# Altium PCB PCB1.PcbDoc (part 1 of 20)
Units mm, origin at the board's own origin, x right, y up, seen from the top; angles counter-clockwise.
Board outline 294.51 x 138.18 mm, 12 copper layers (Top Layer 1 _Signal, L2_GND, L3_Signals, L4_GND, L5_POWER, L6_Signals, L7_GND, L8_Signals, L9_GND, L10_POWER, L11_GND, Bottom Layer_Signals), stack 1.788 mm thick; 1254 components, 836 nets, 5699 pads, 2073 vias.
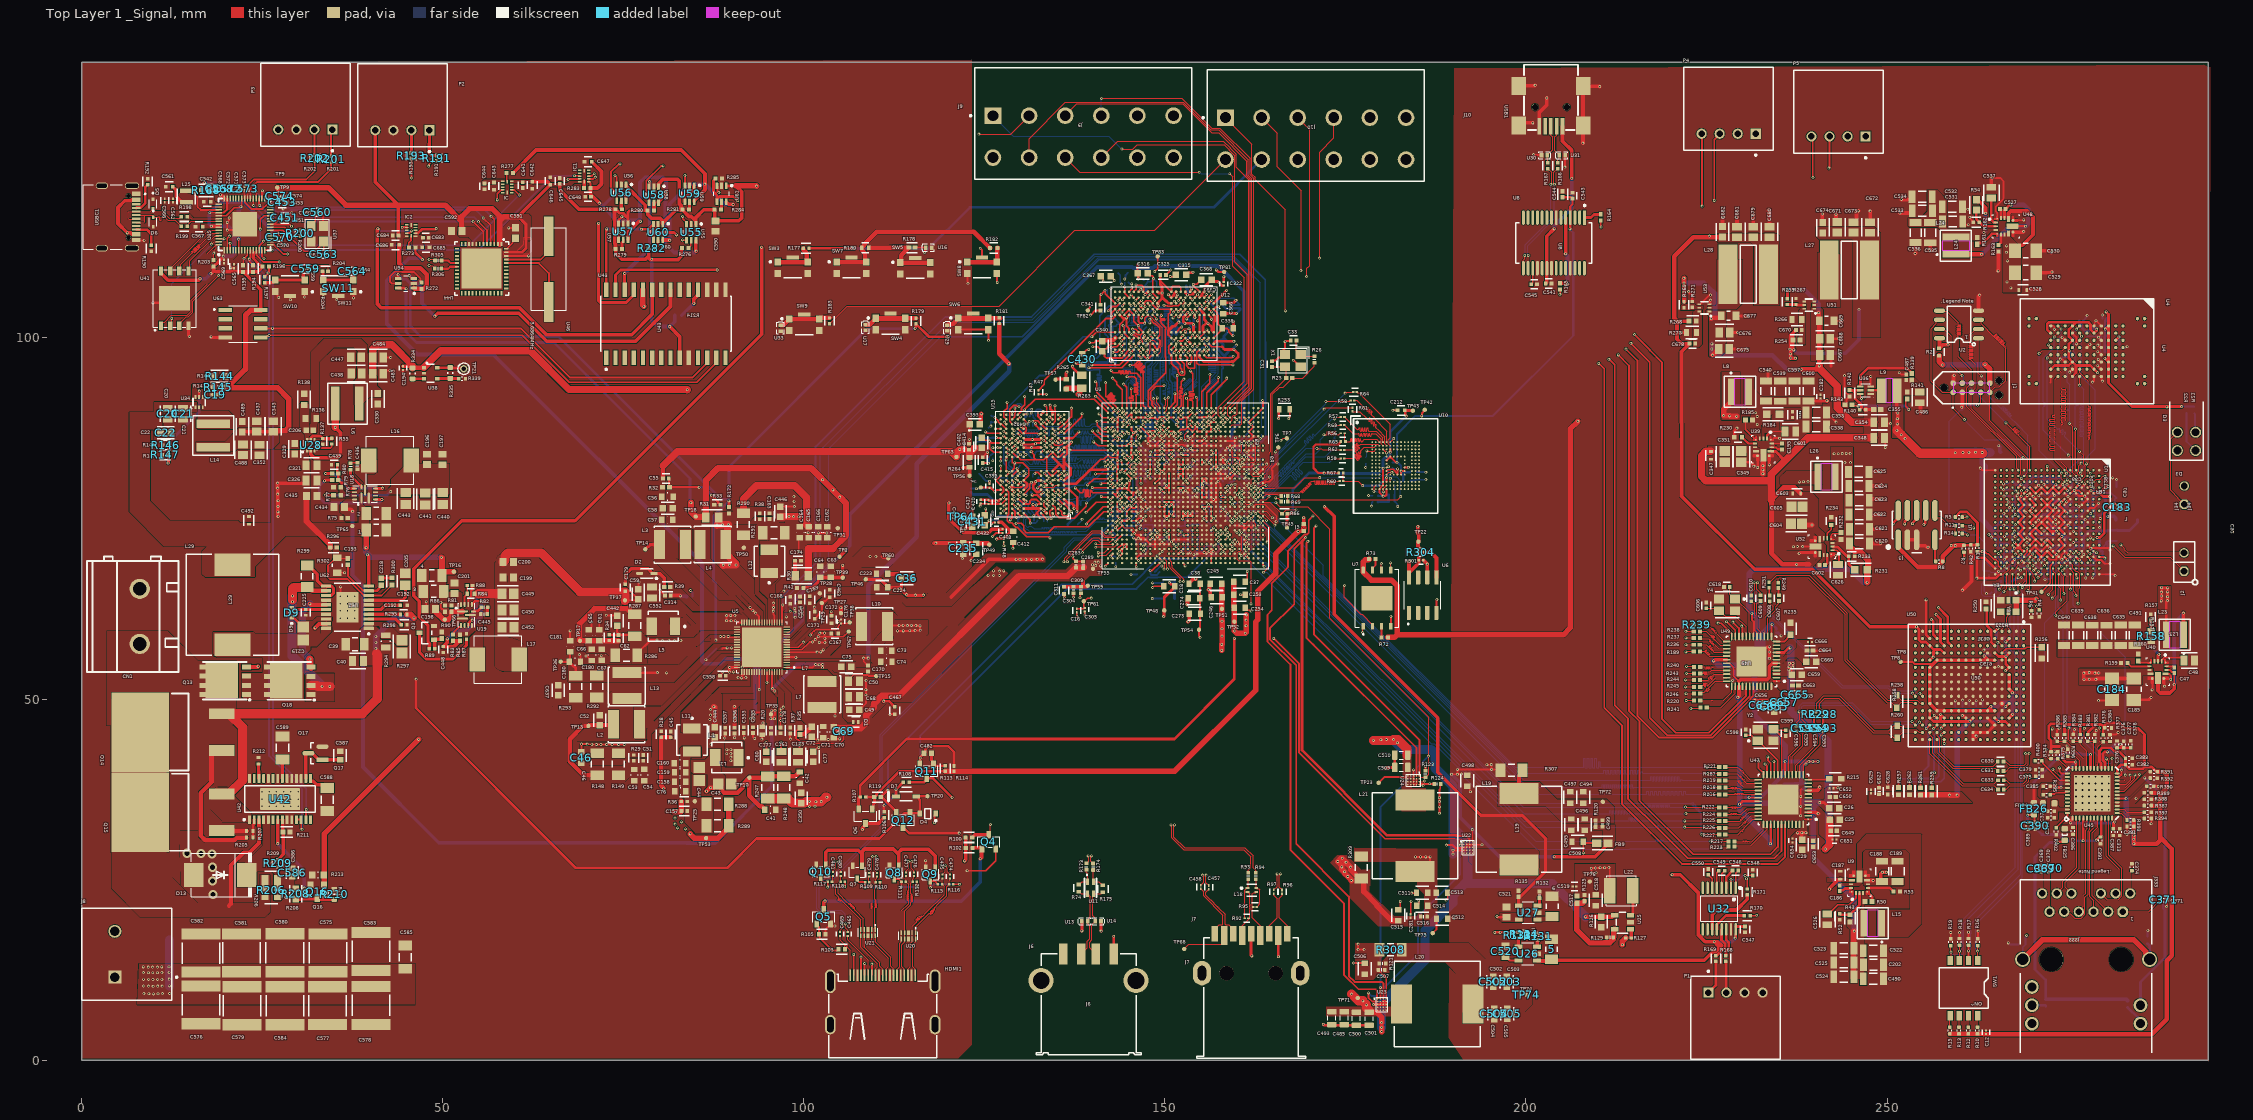
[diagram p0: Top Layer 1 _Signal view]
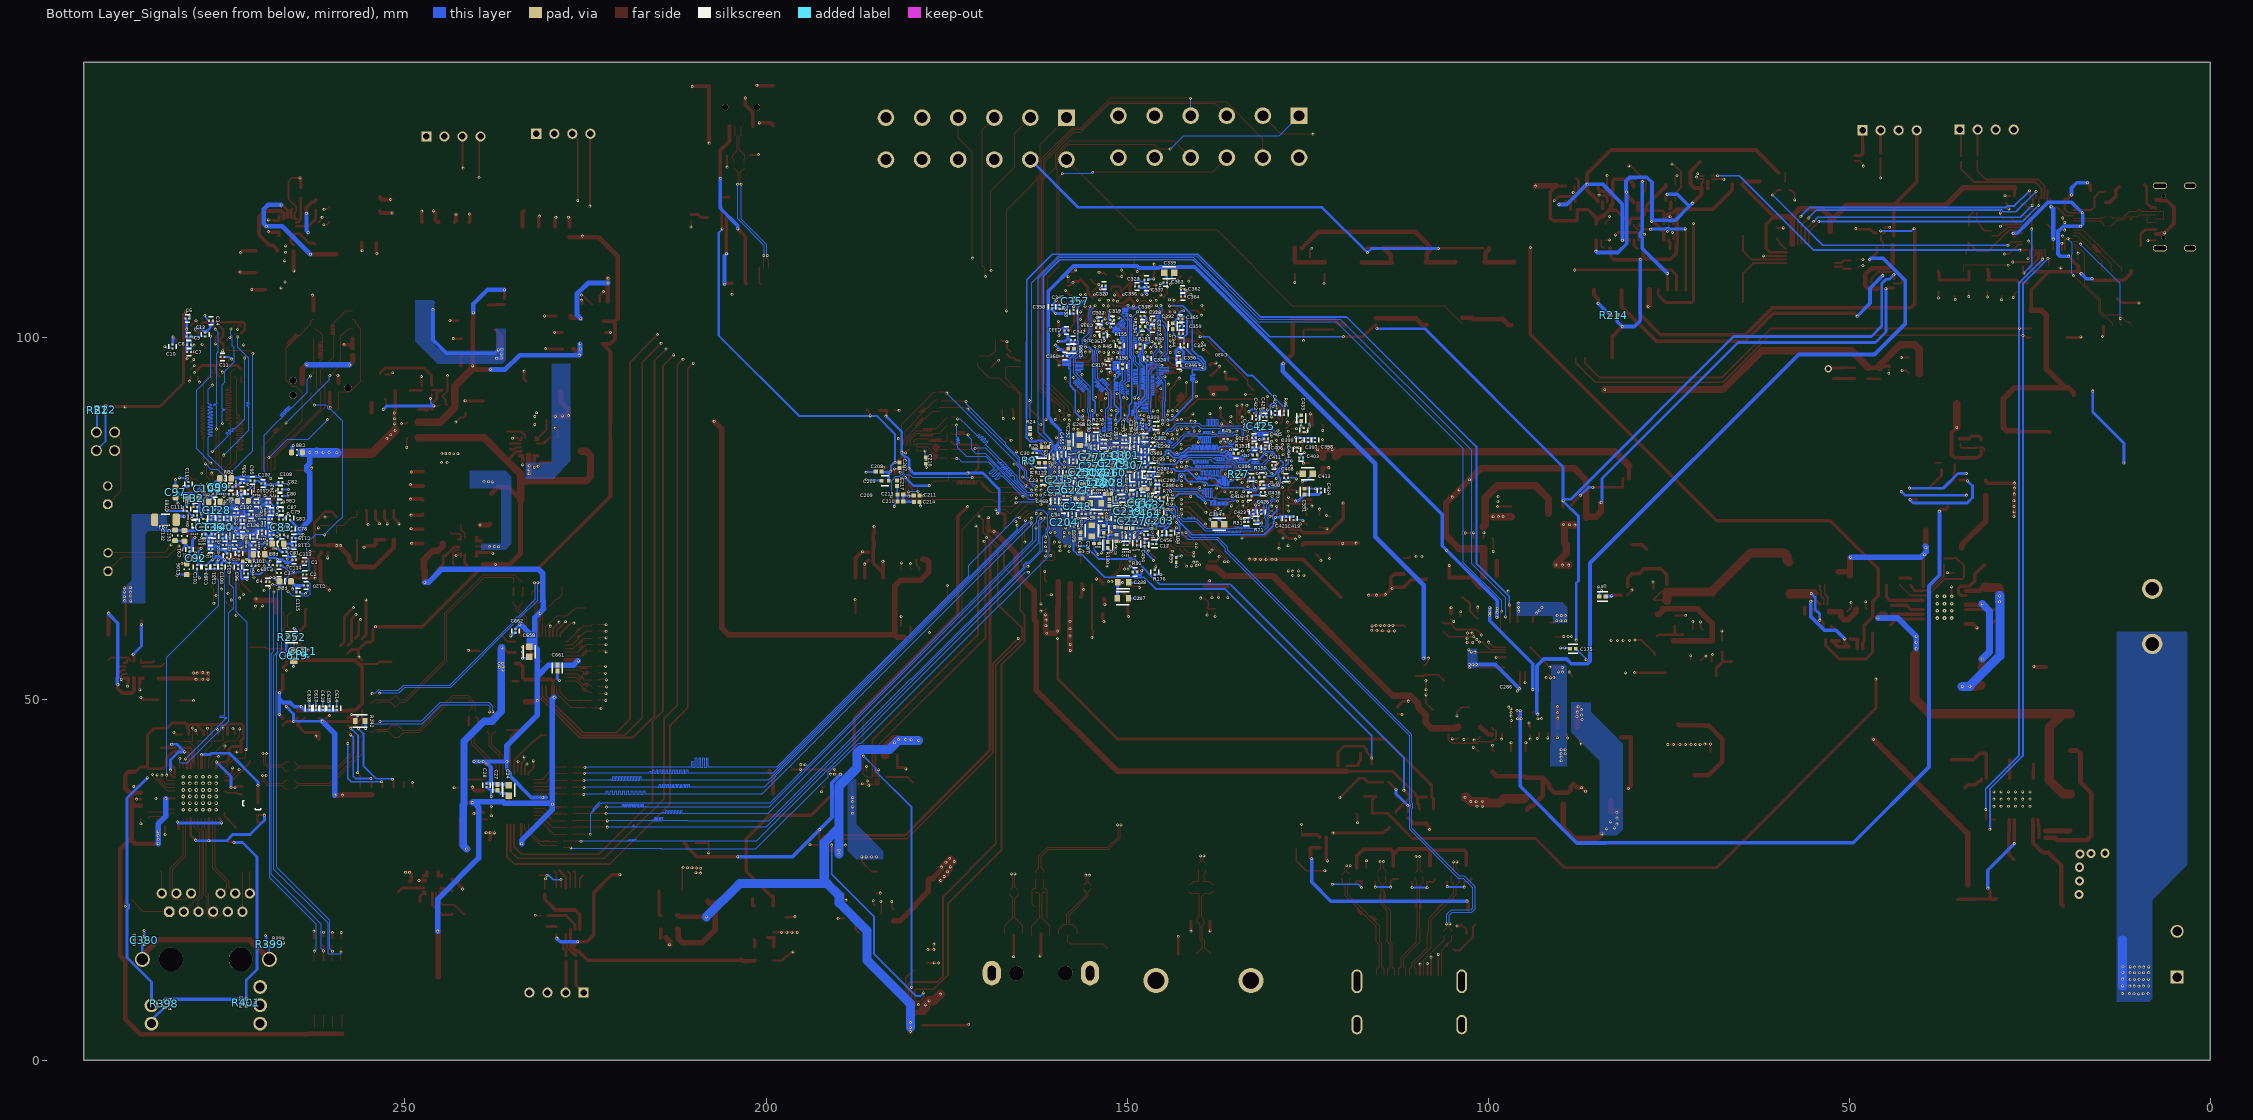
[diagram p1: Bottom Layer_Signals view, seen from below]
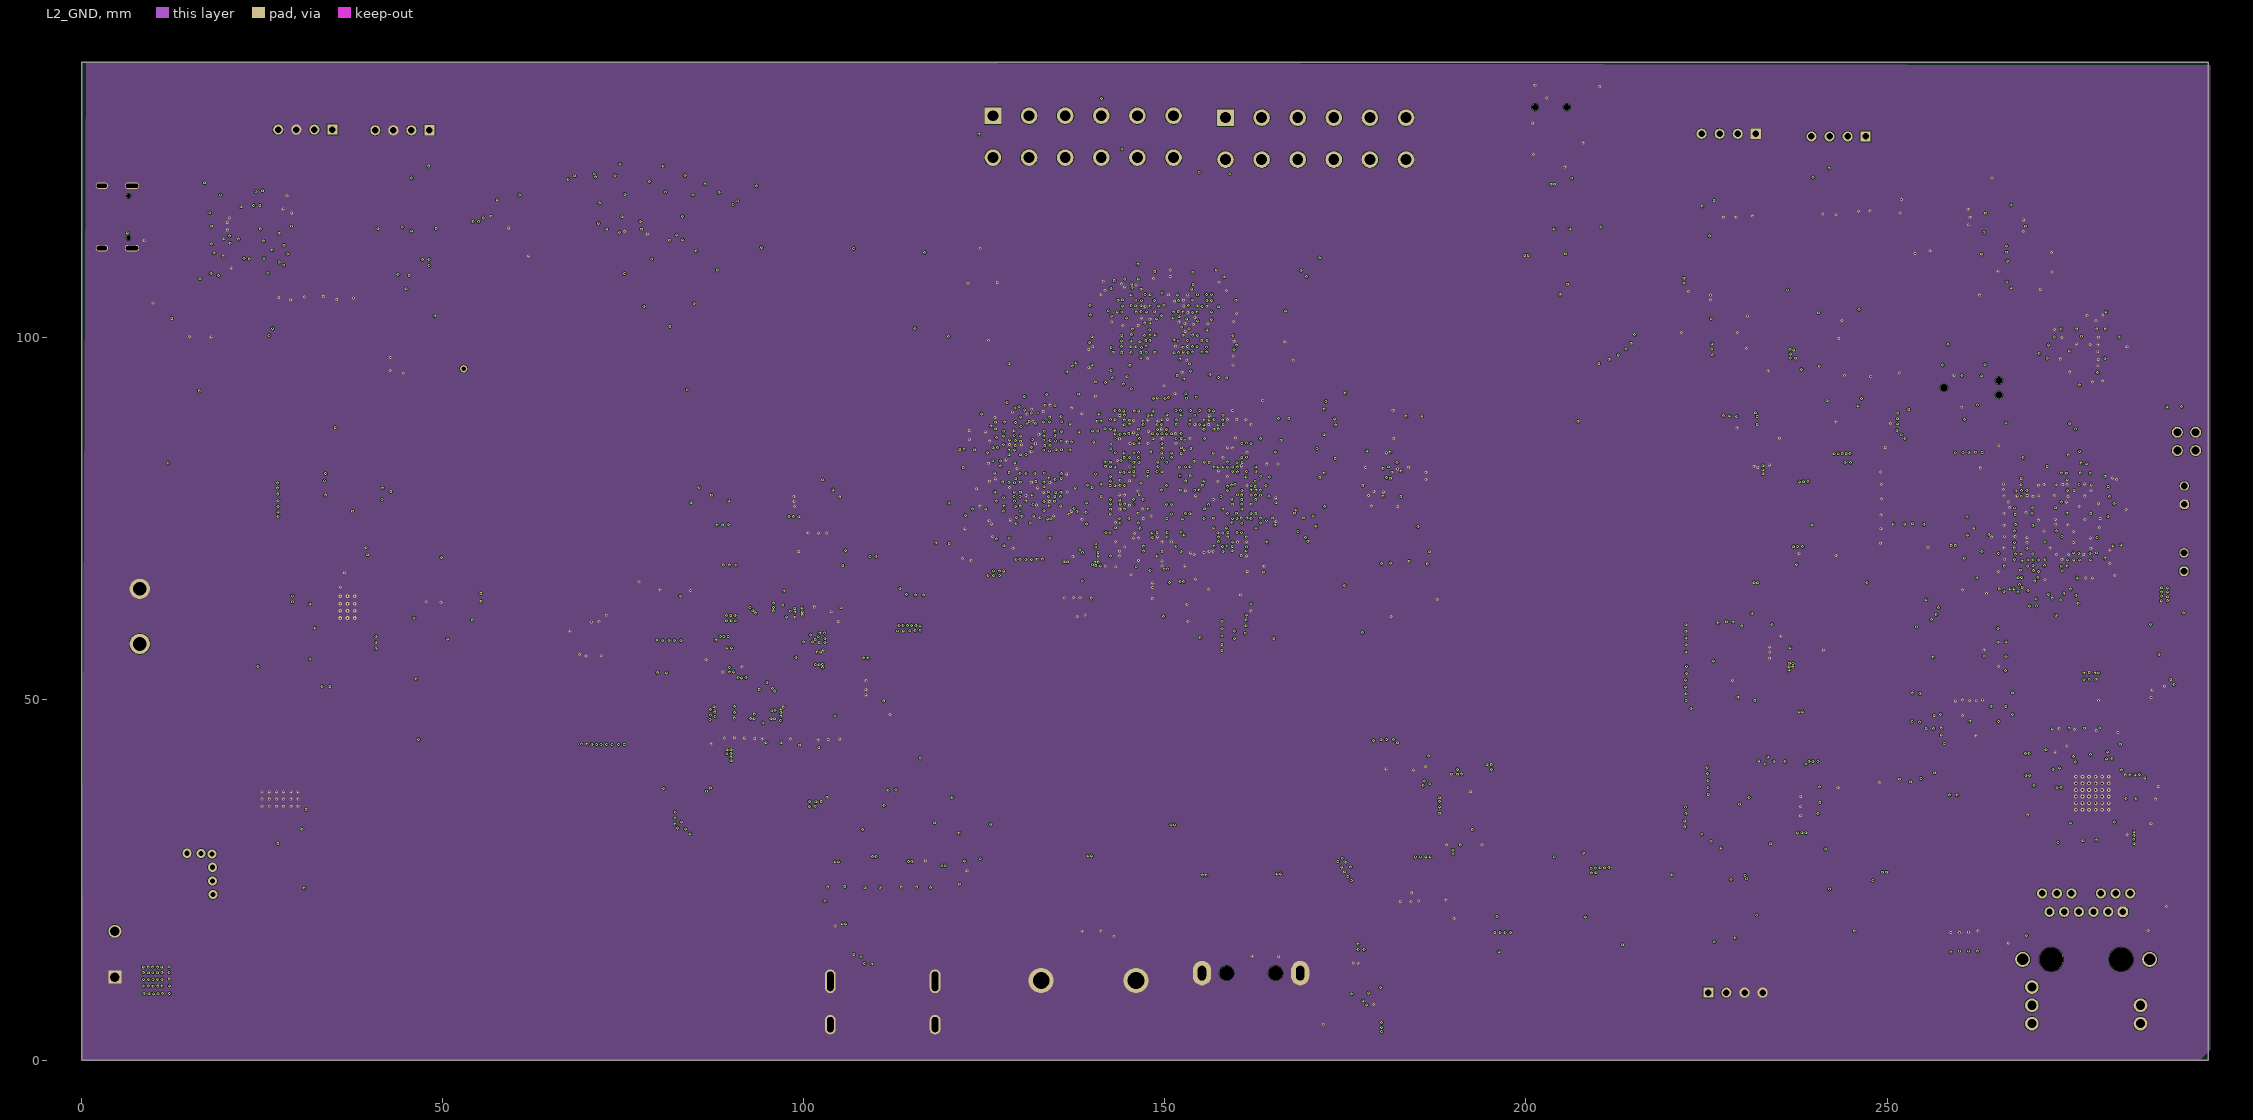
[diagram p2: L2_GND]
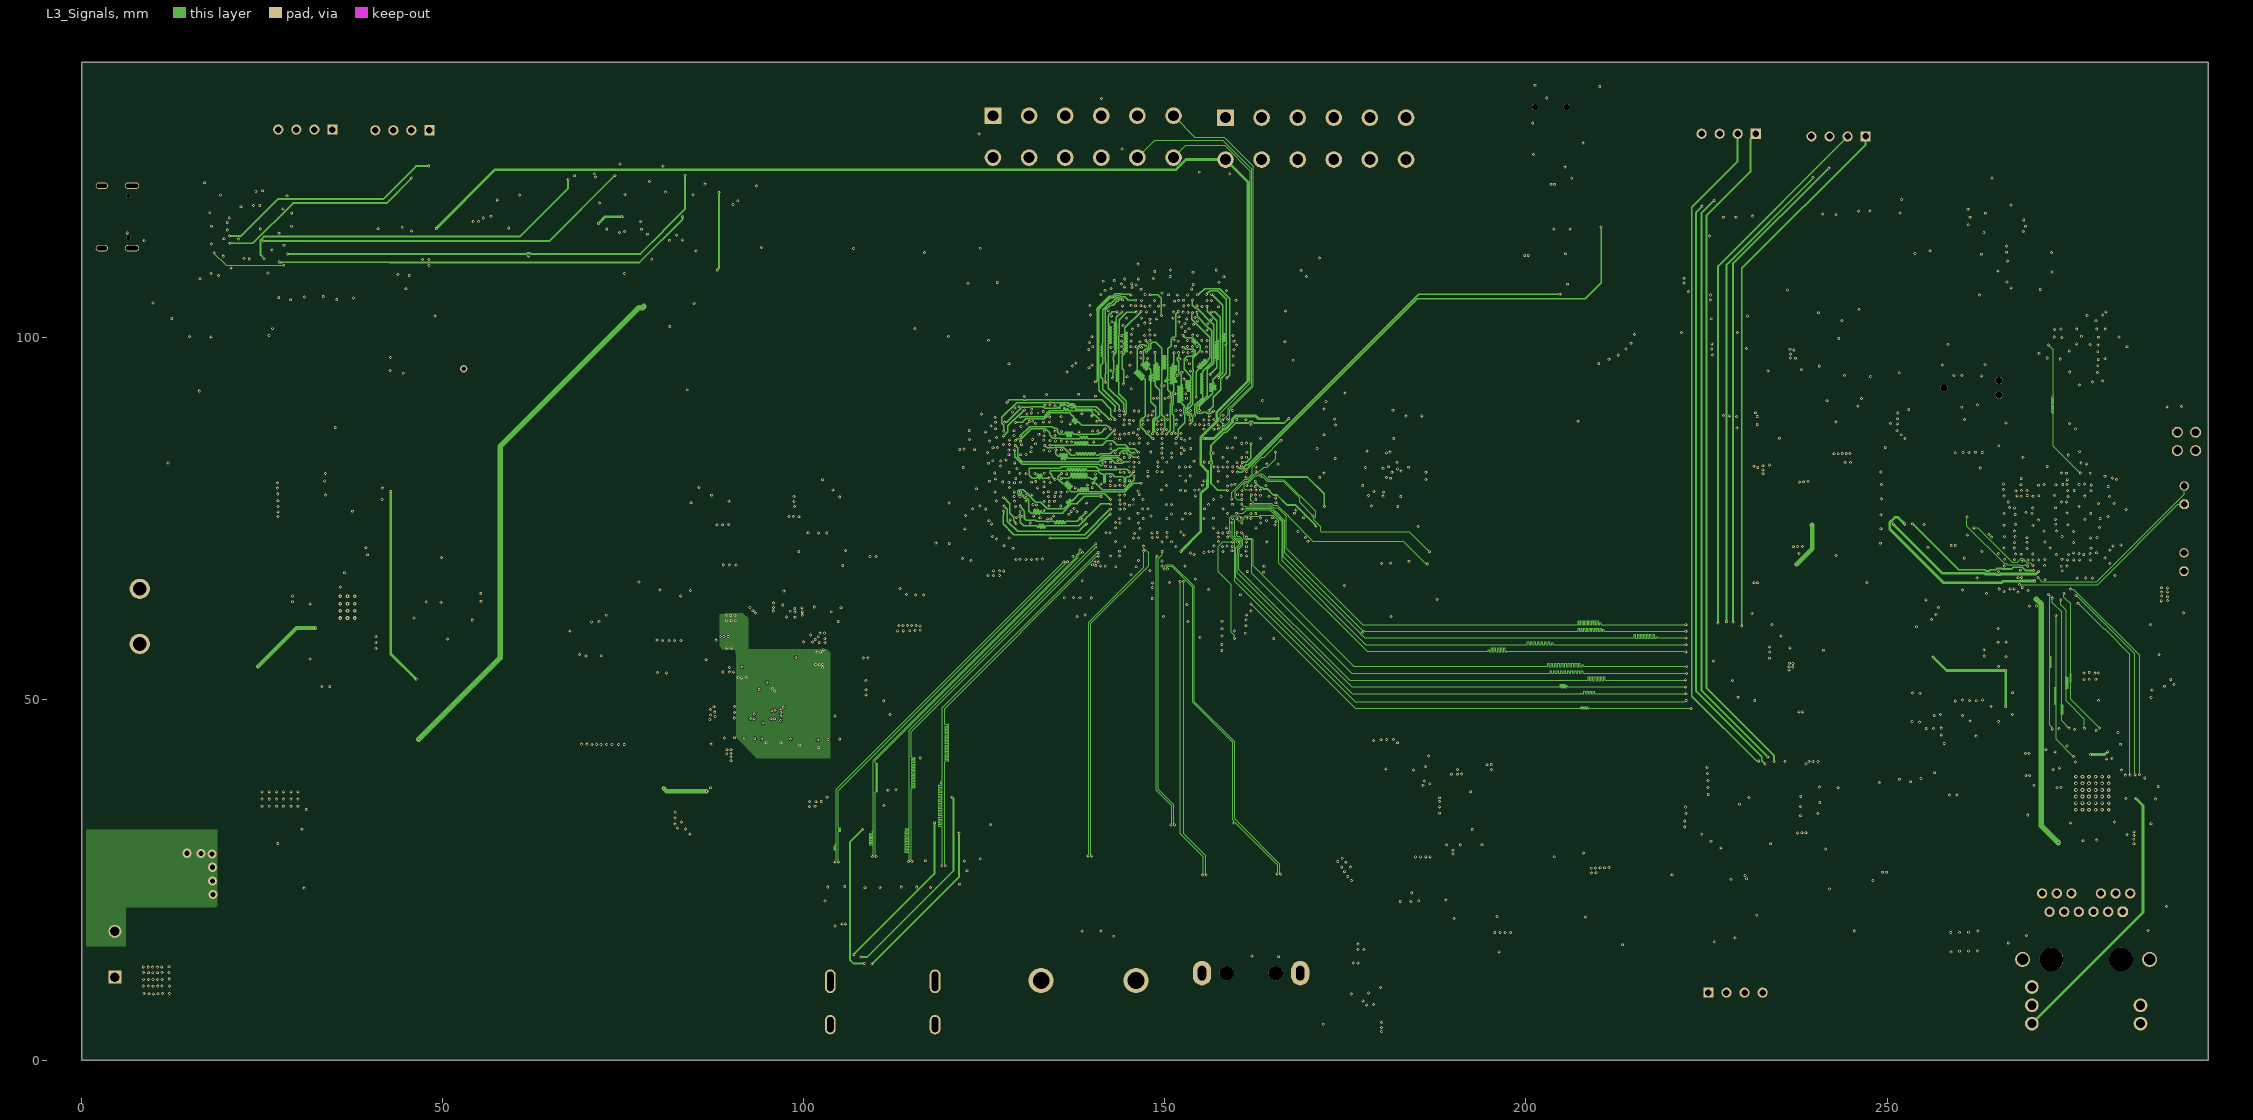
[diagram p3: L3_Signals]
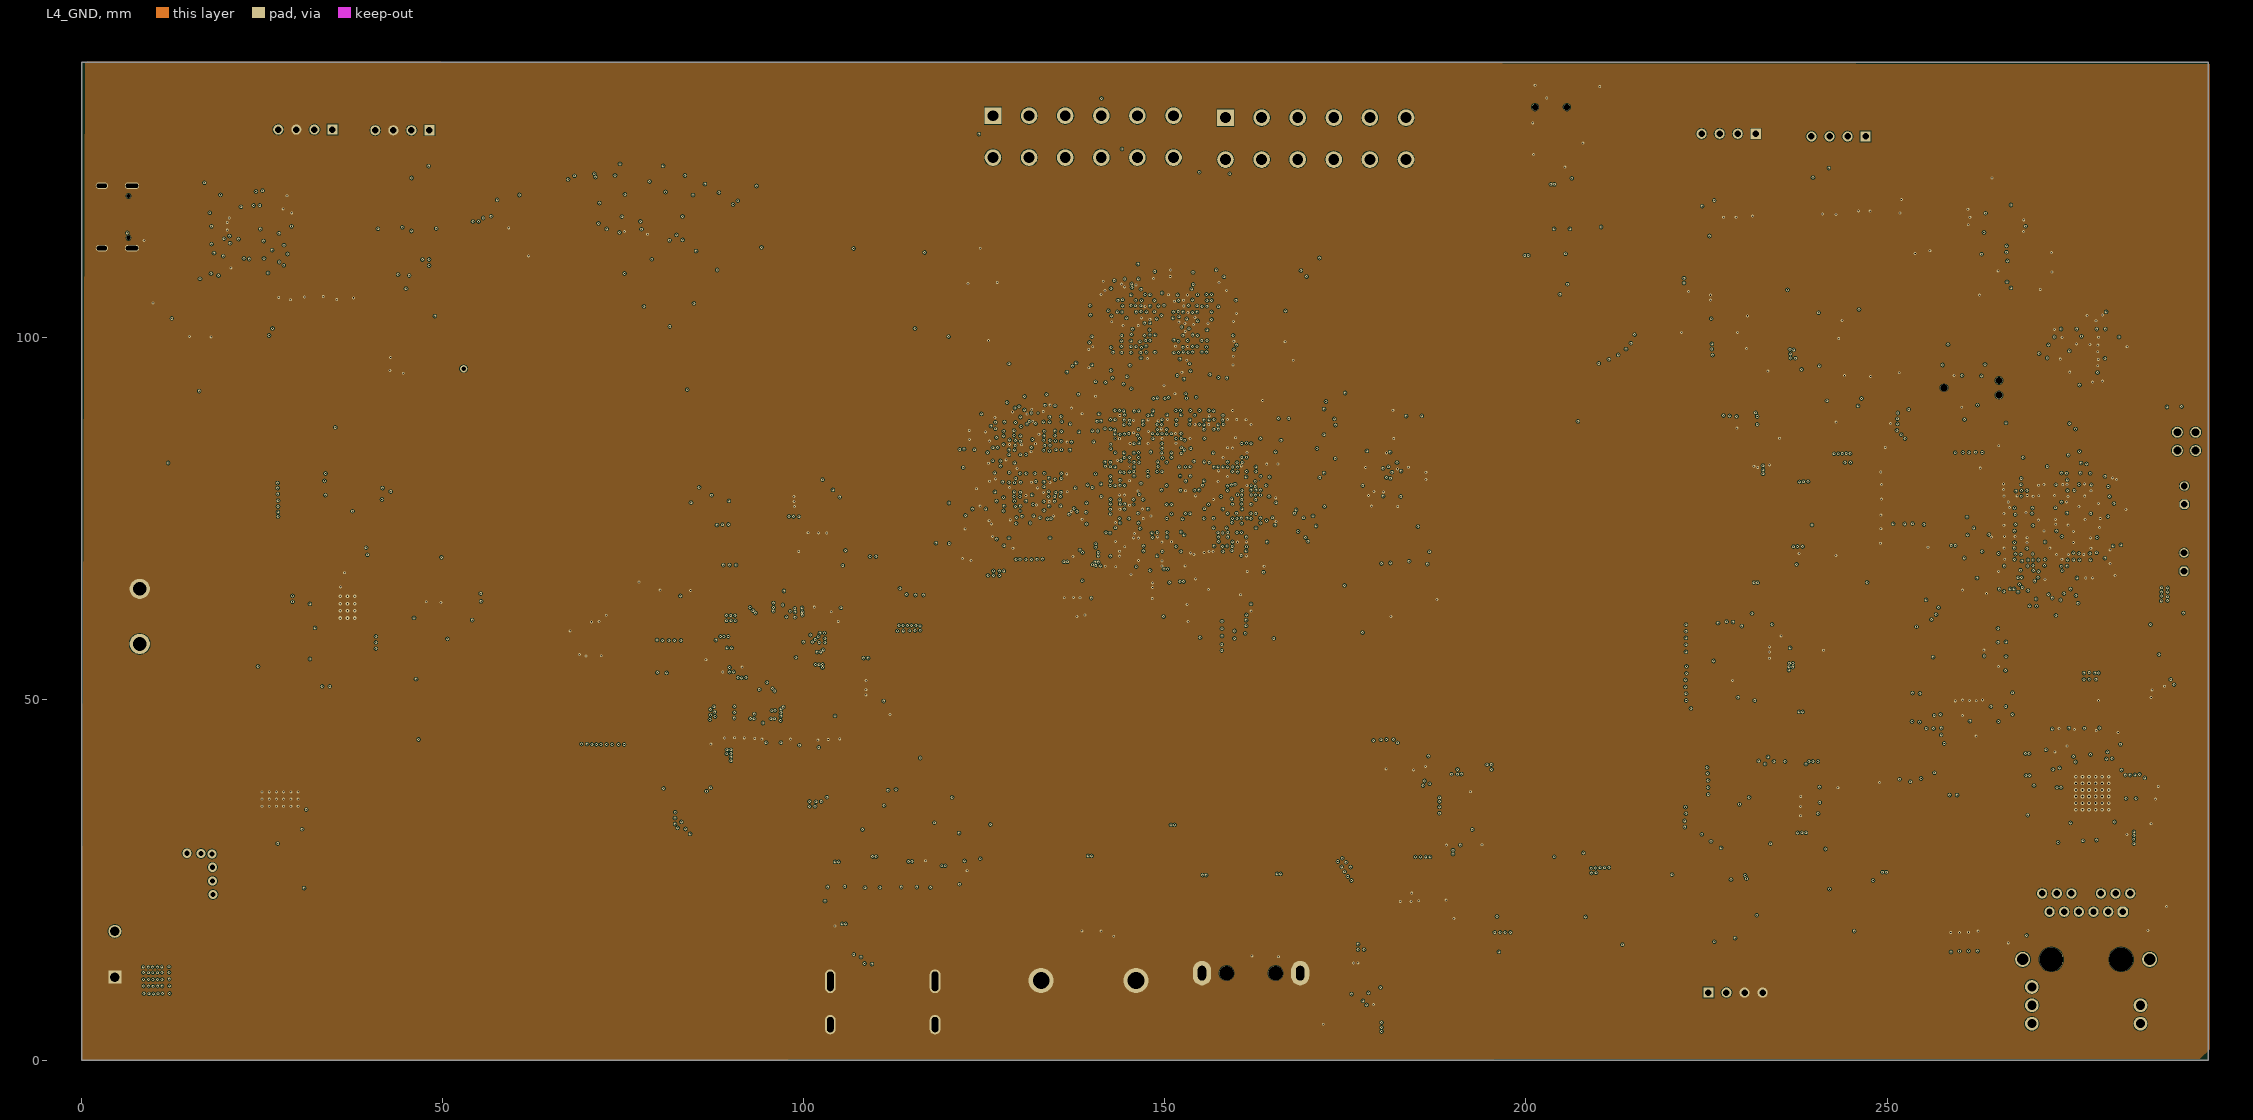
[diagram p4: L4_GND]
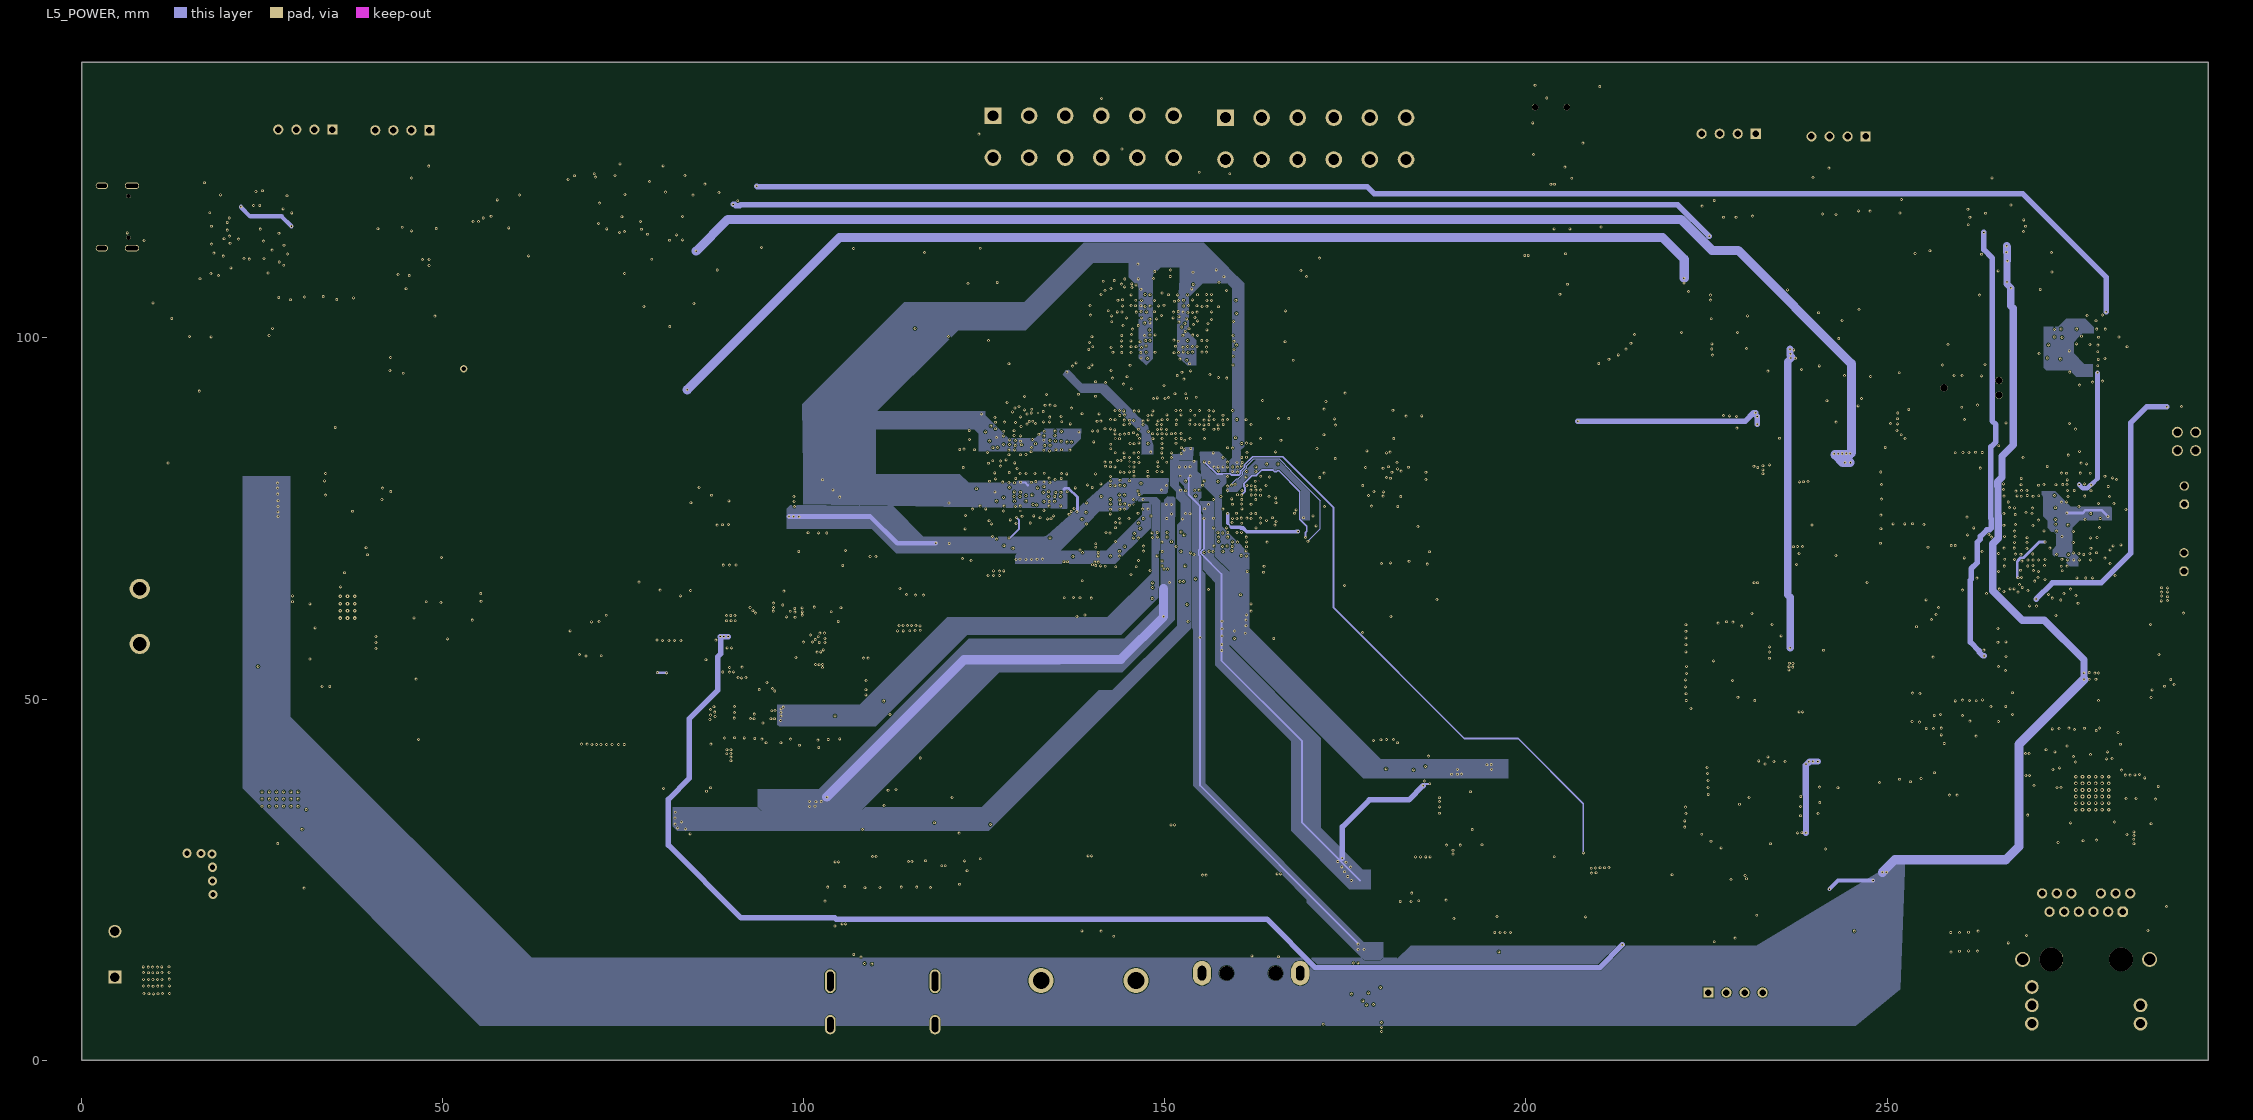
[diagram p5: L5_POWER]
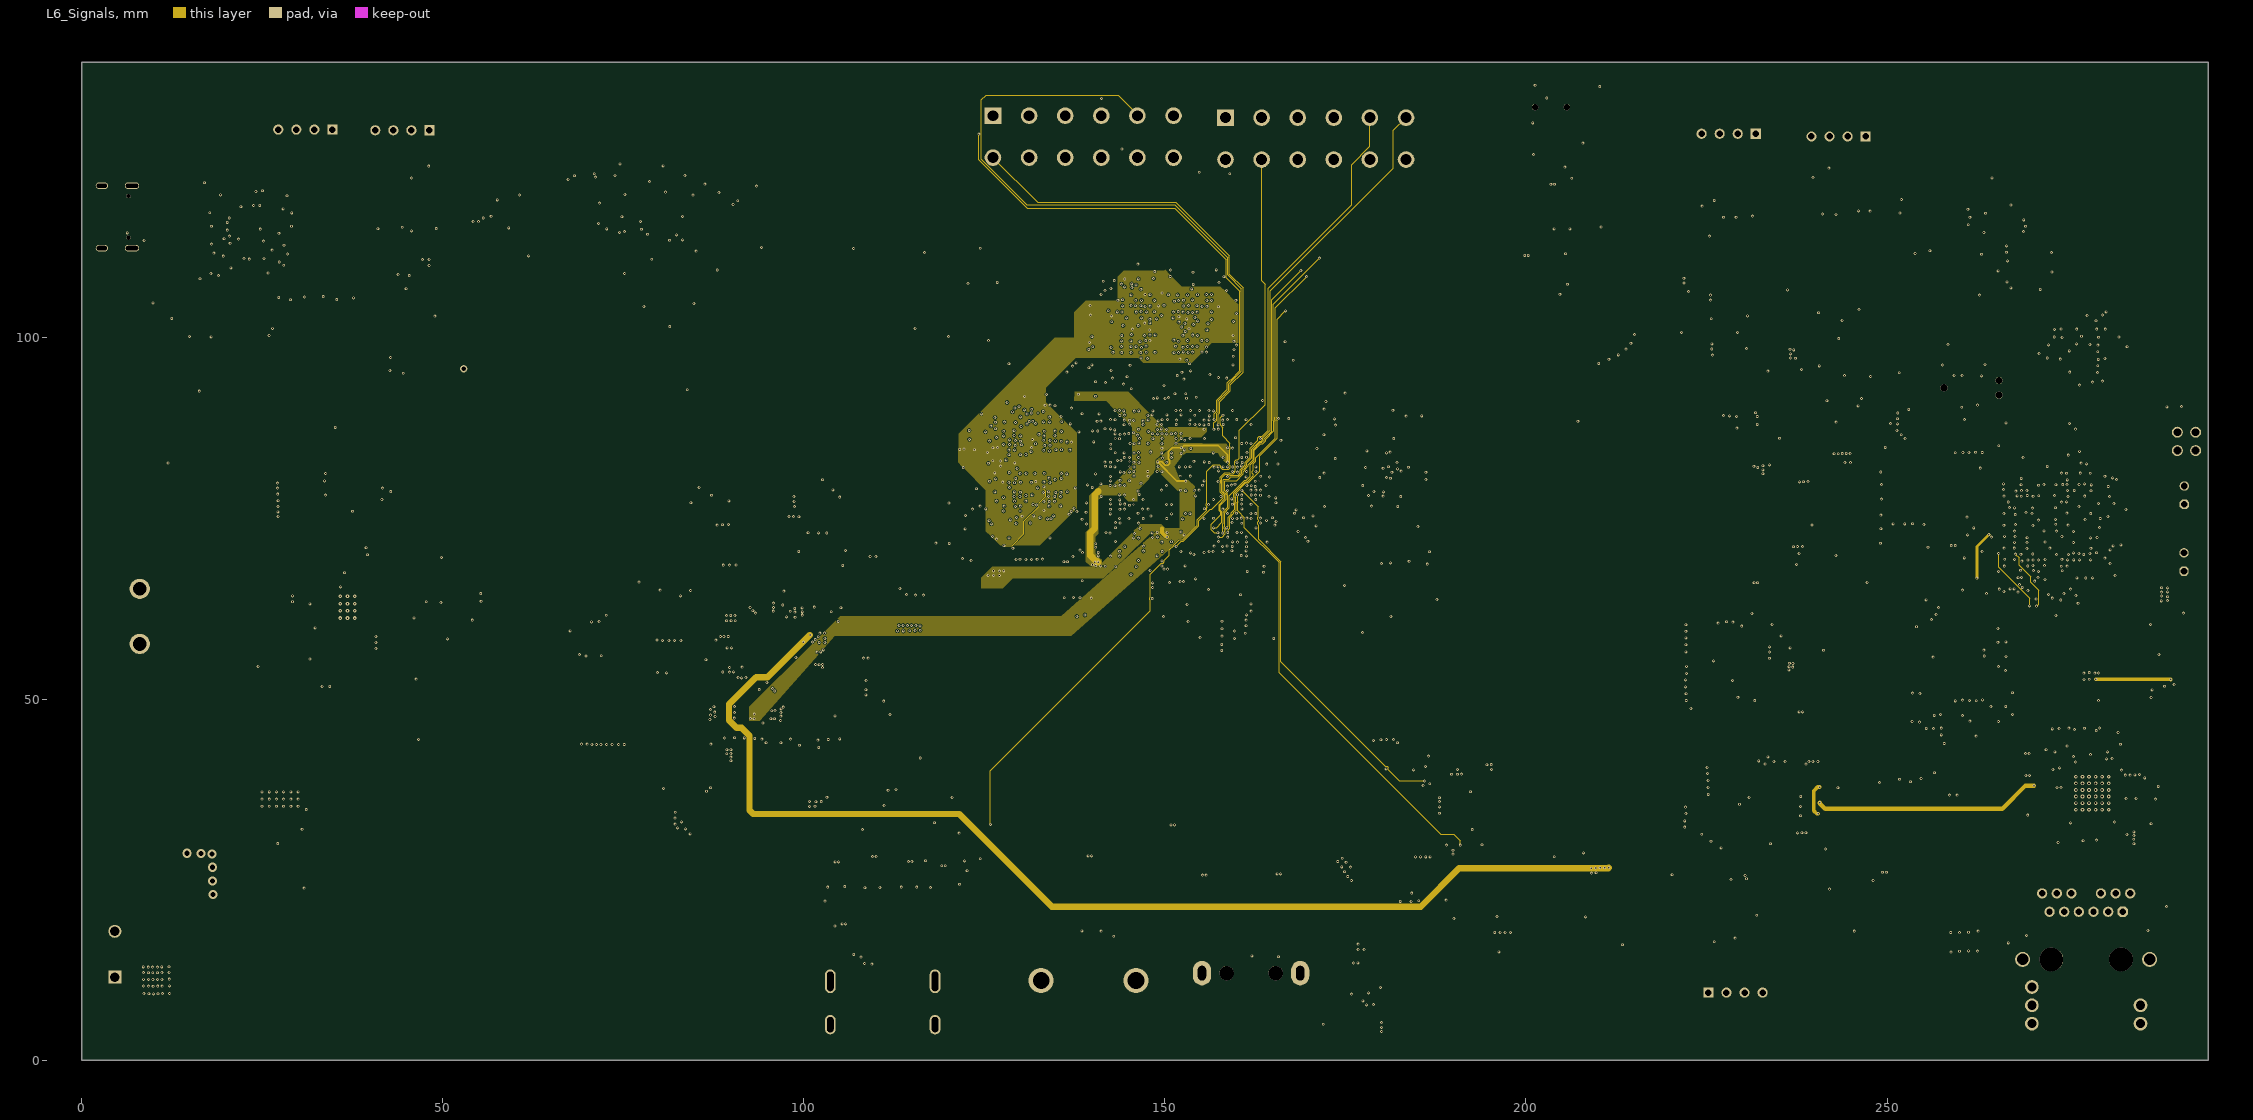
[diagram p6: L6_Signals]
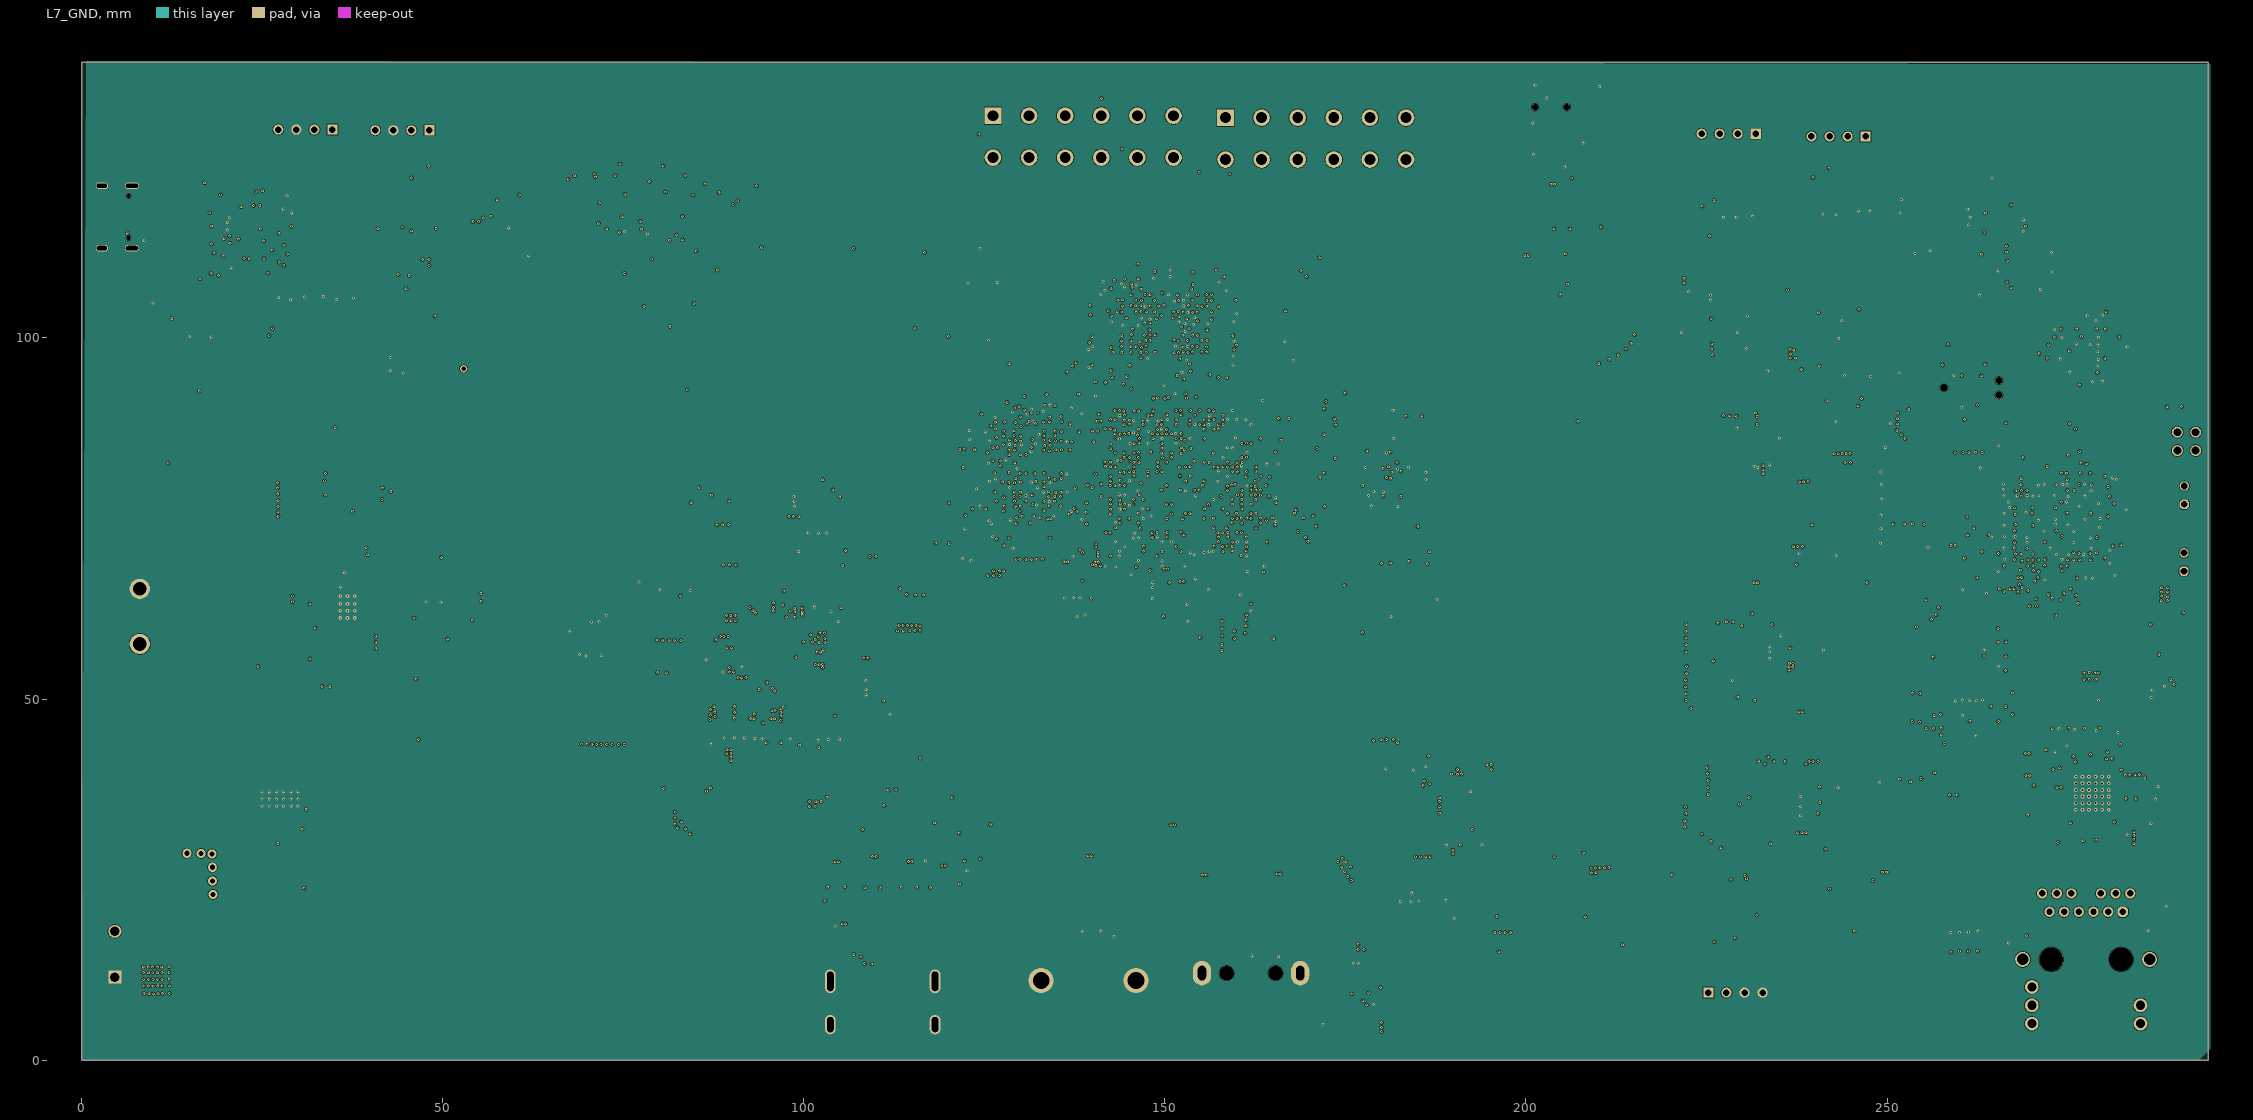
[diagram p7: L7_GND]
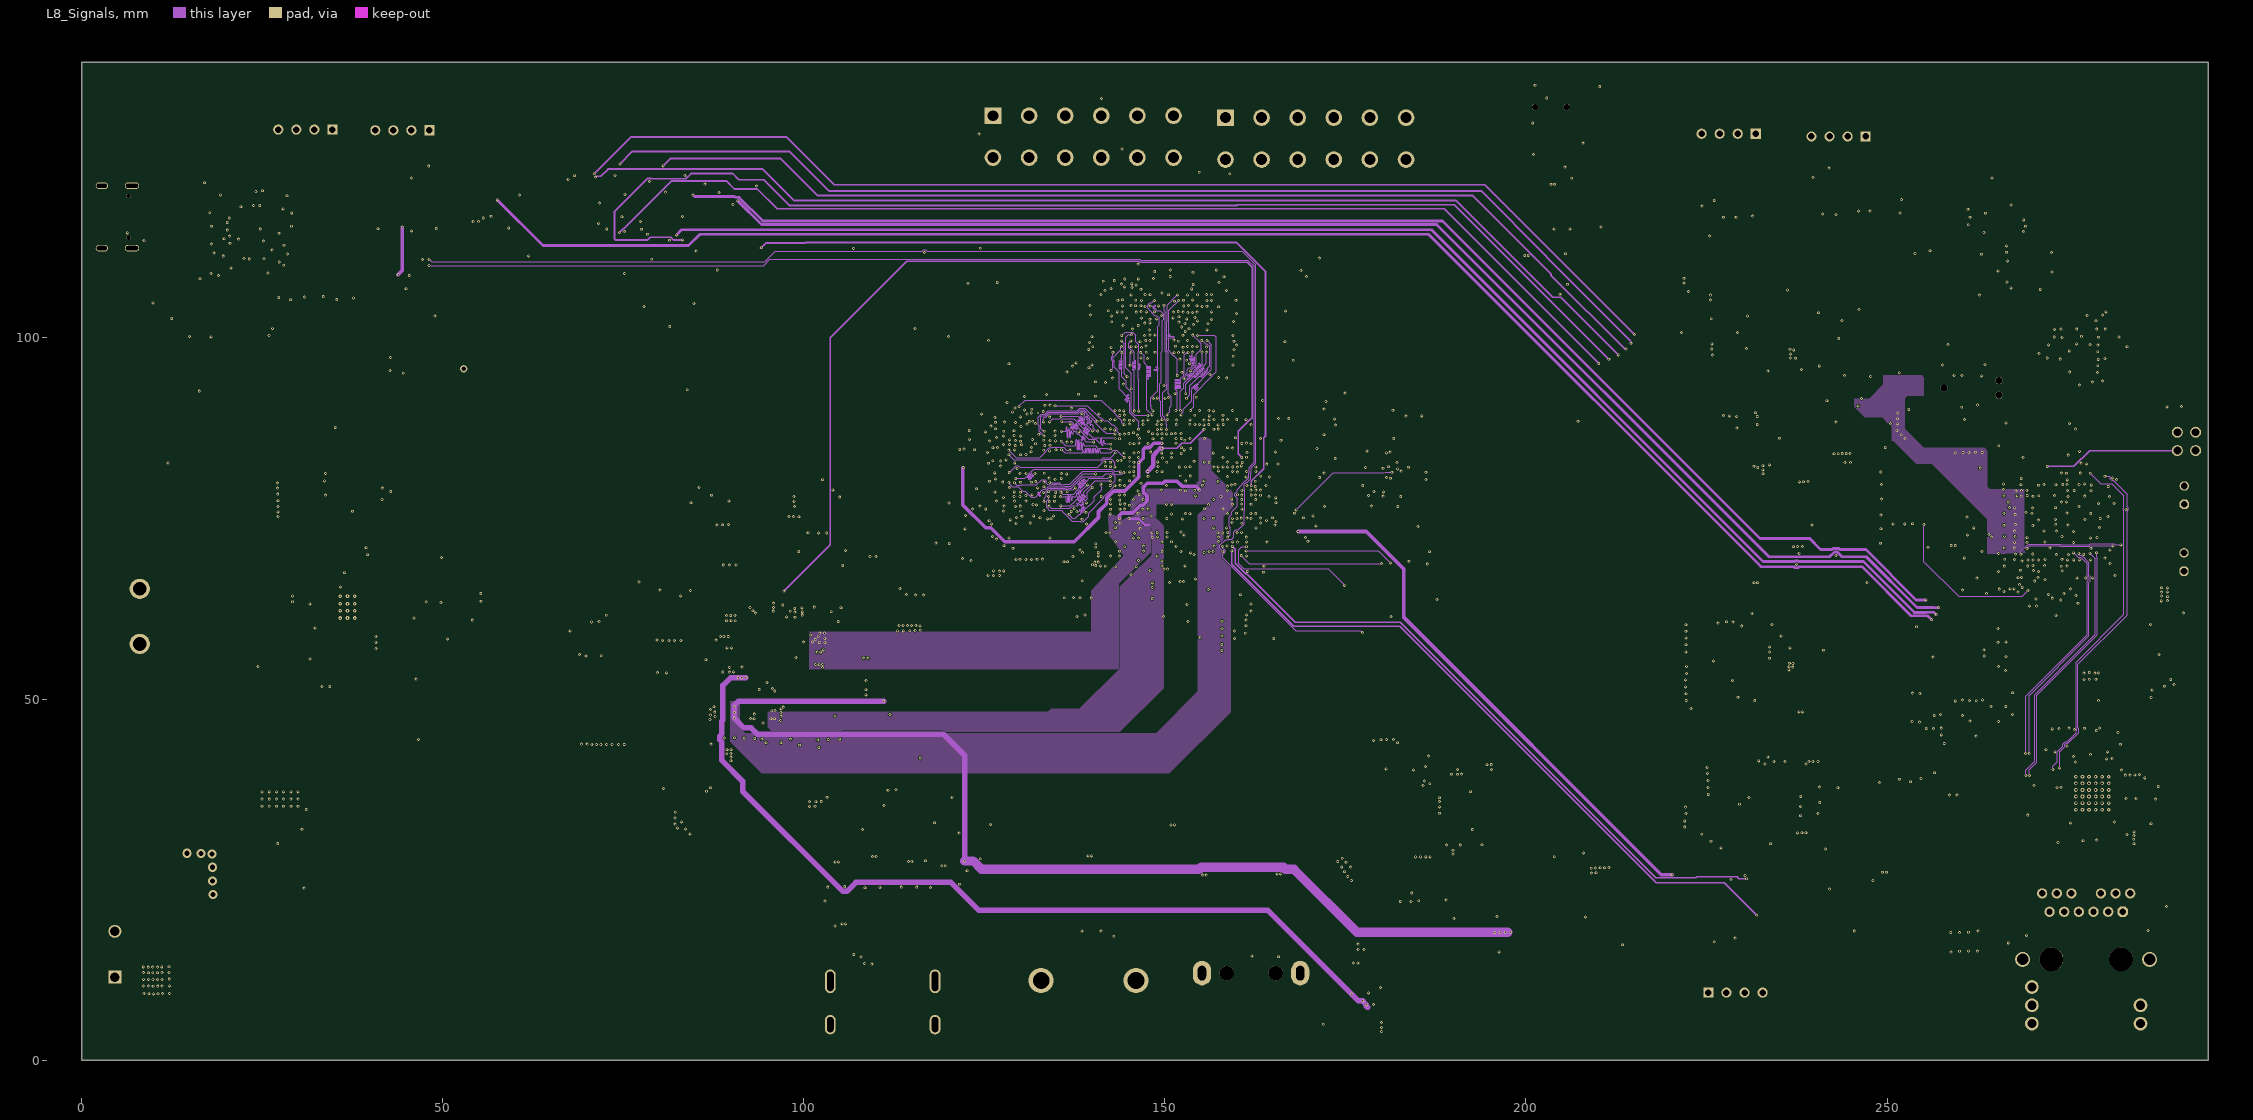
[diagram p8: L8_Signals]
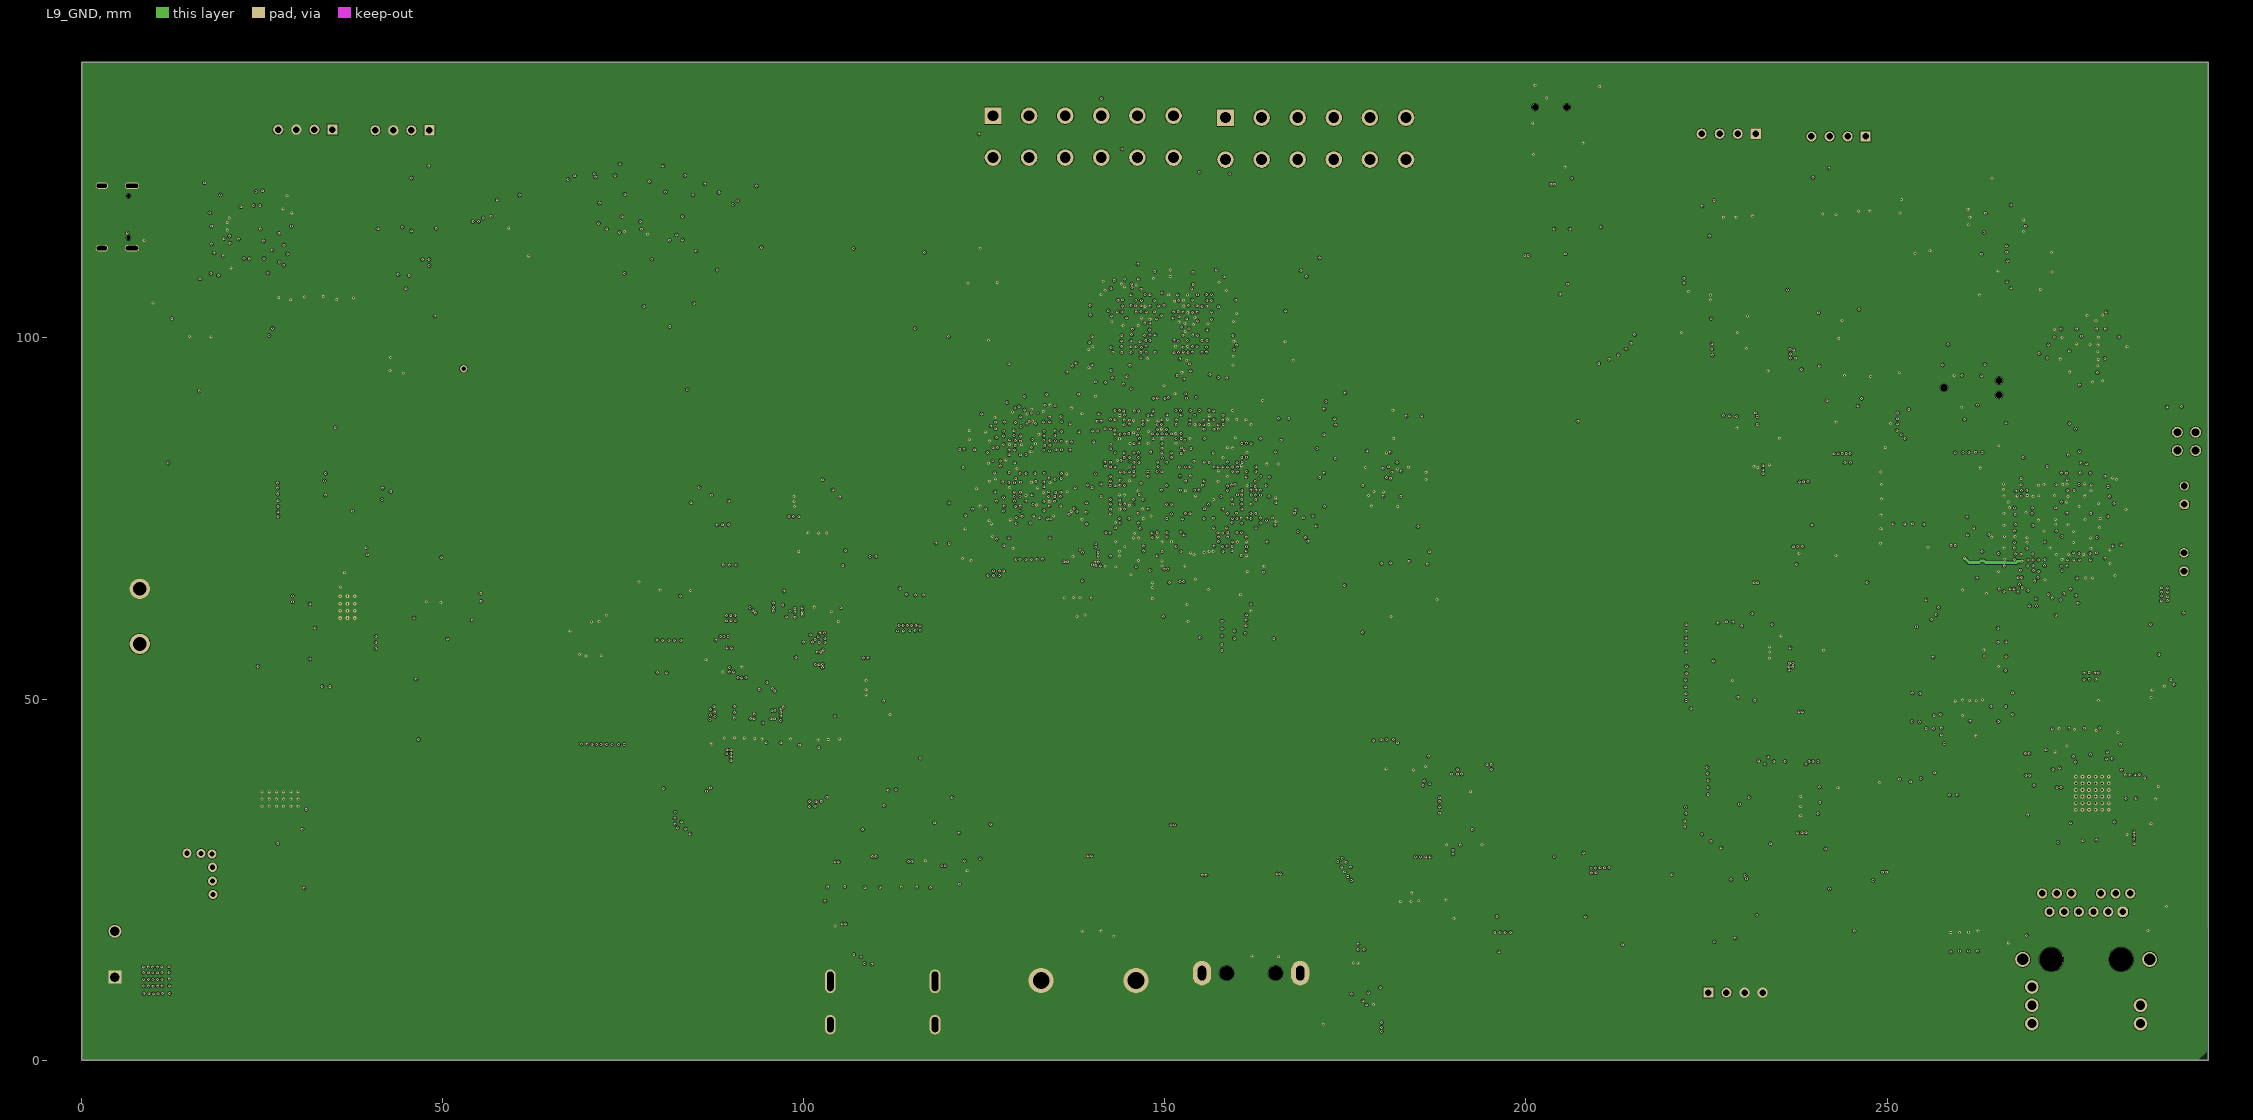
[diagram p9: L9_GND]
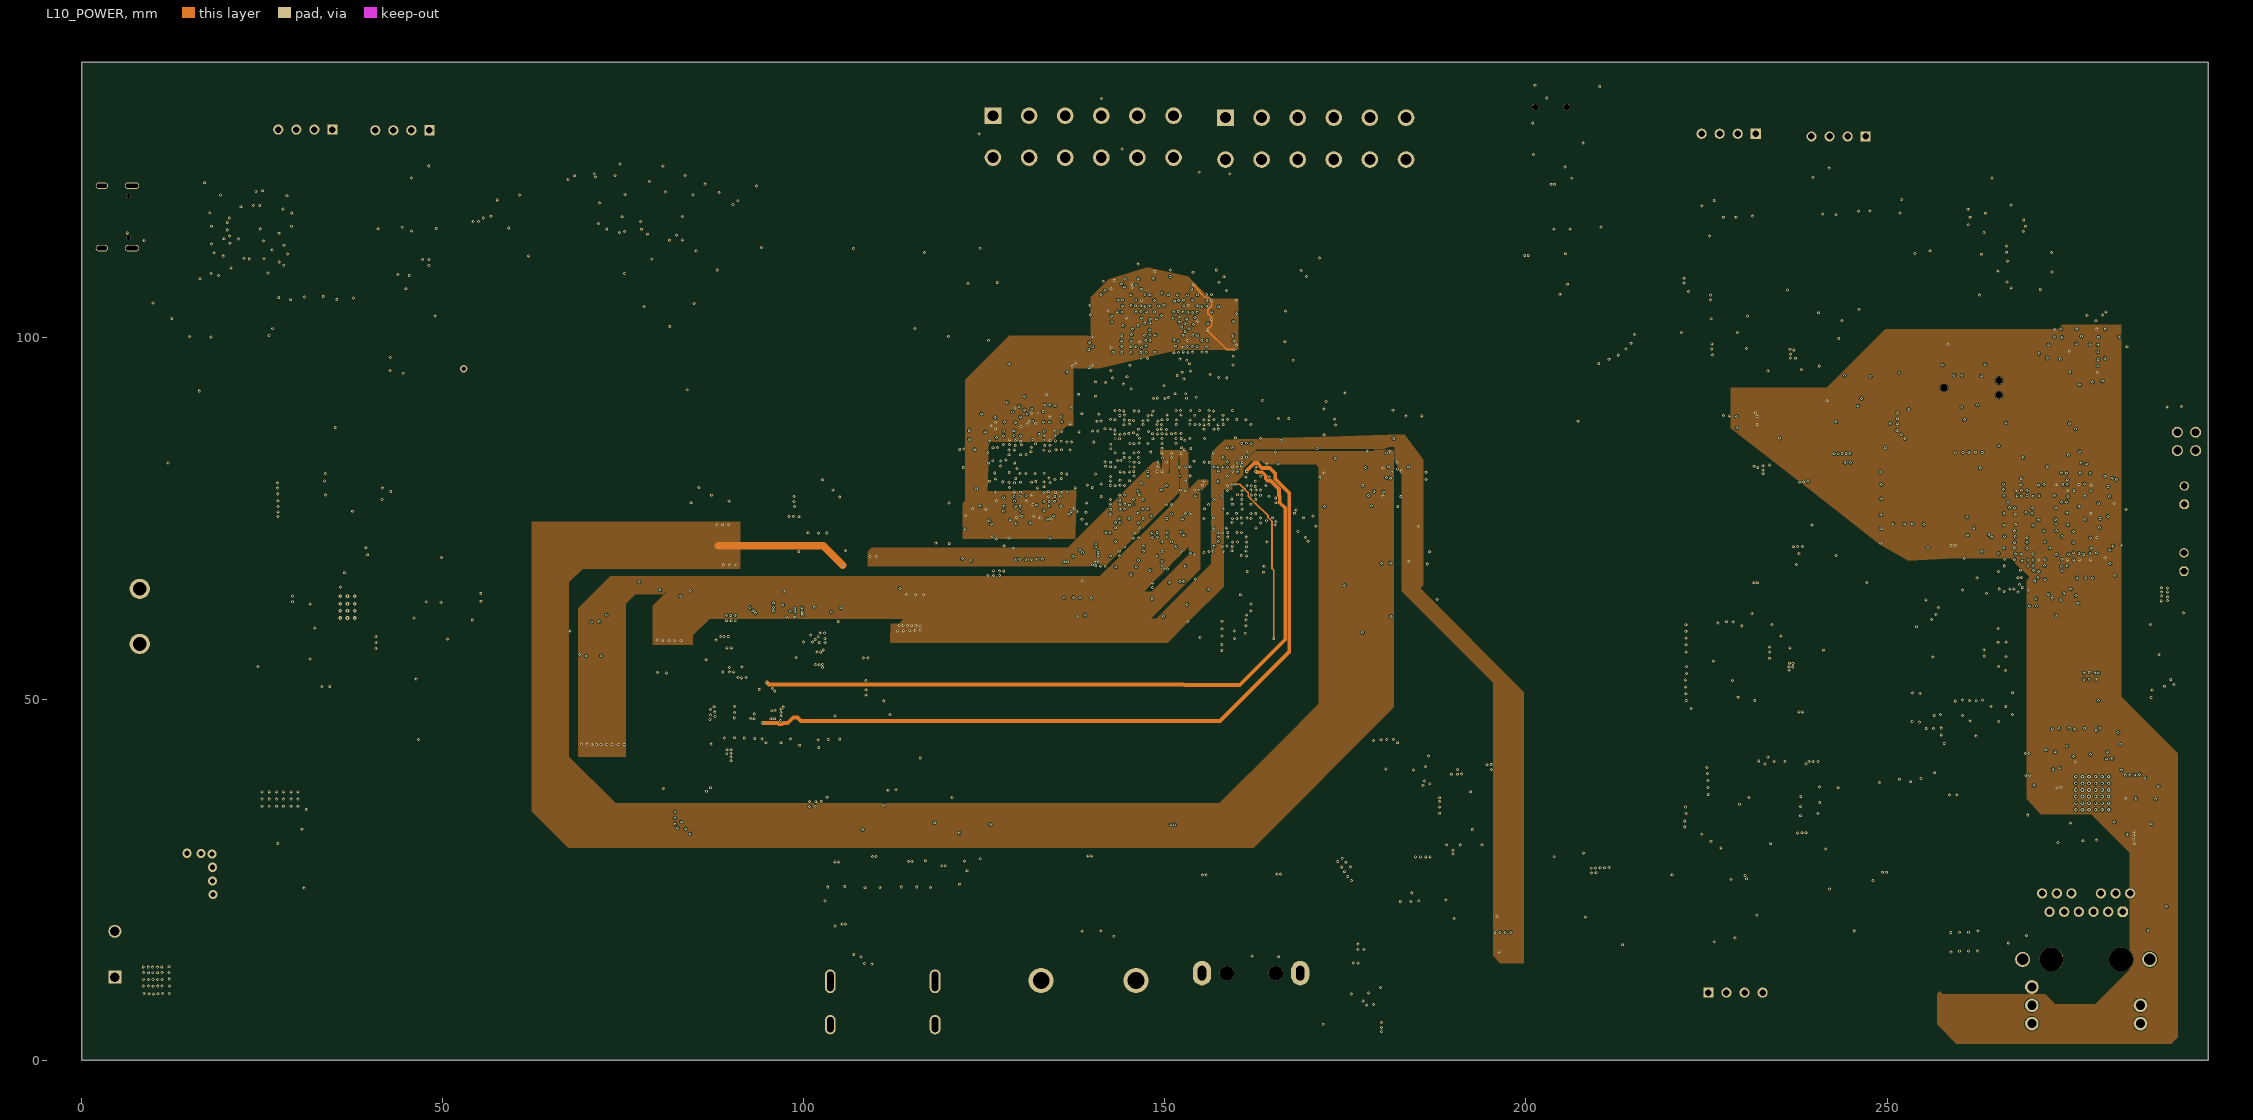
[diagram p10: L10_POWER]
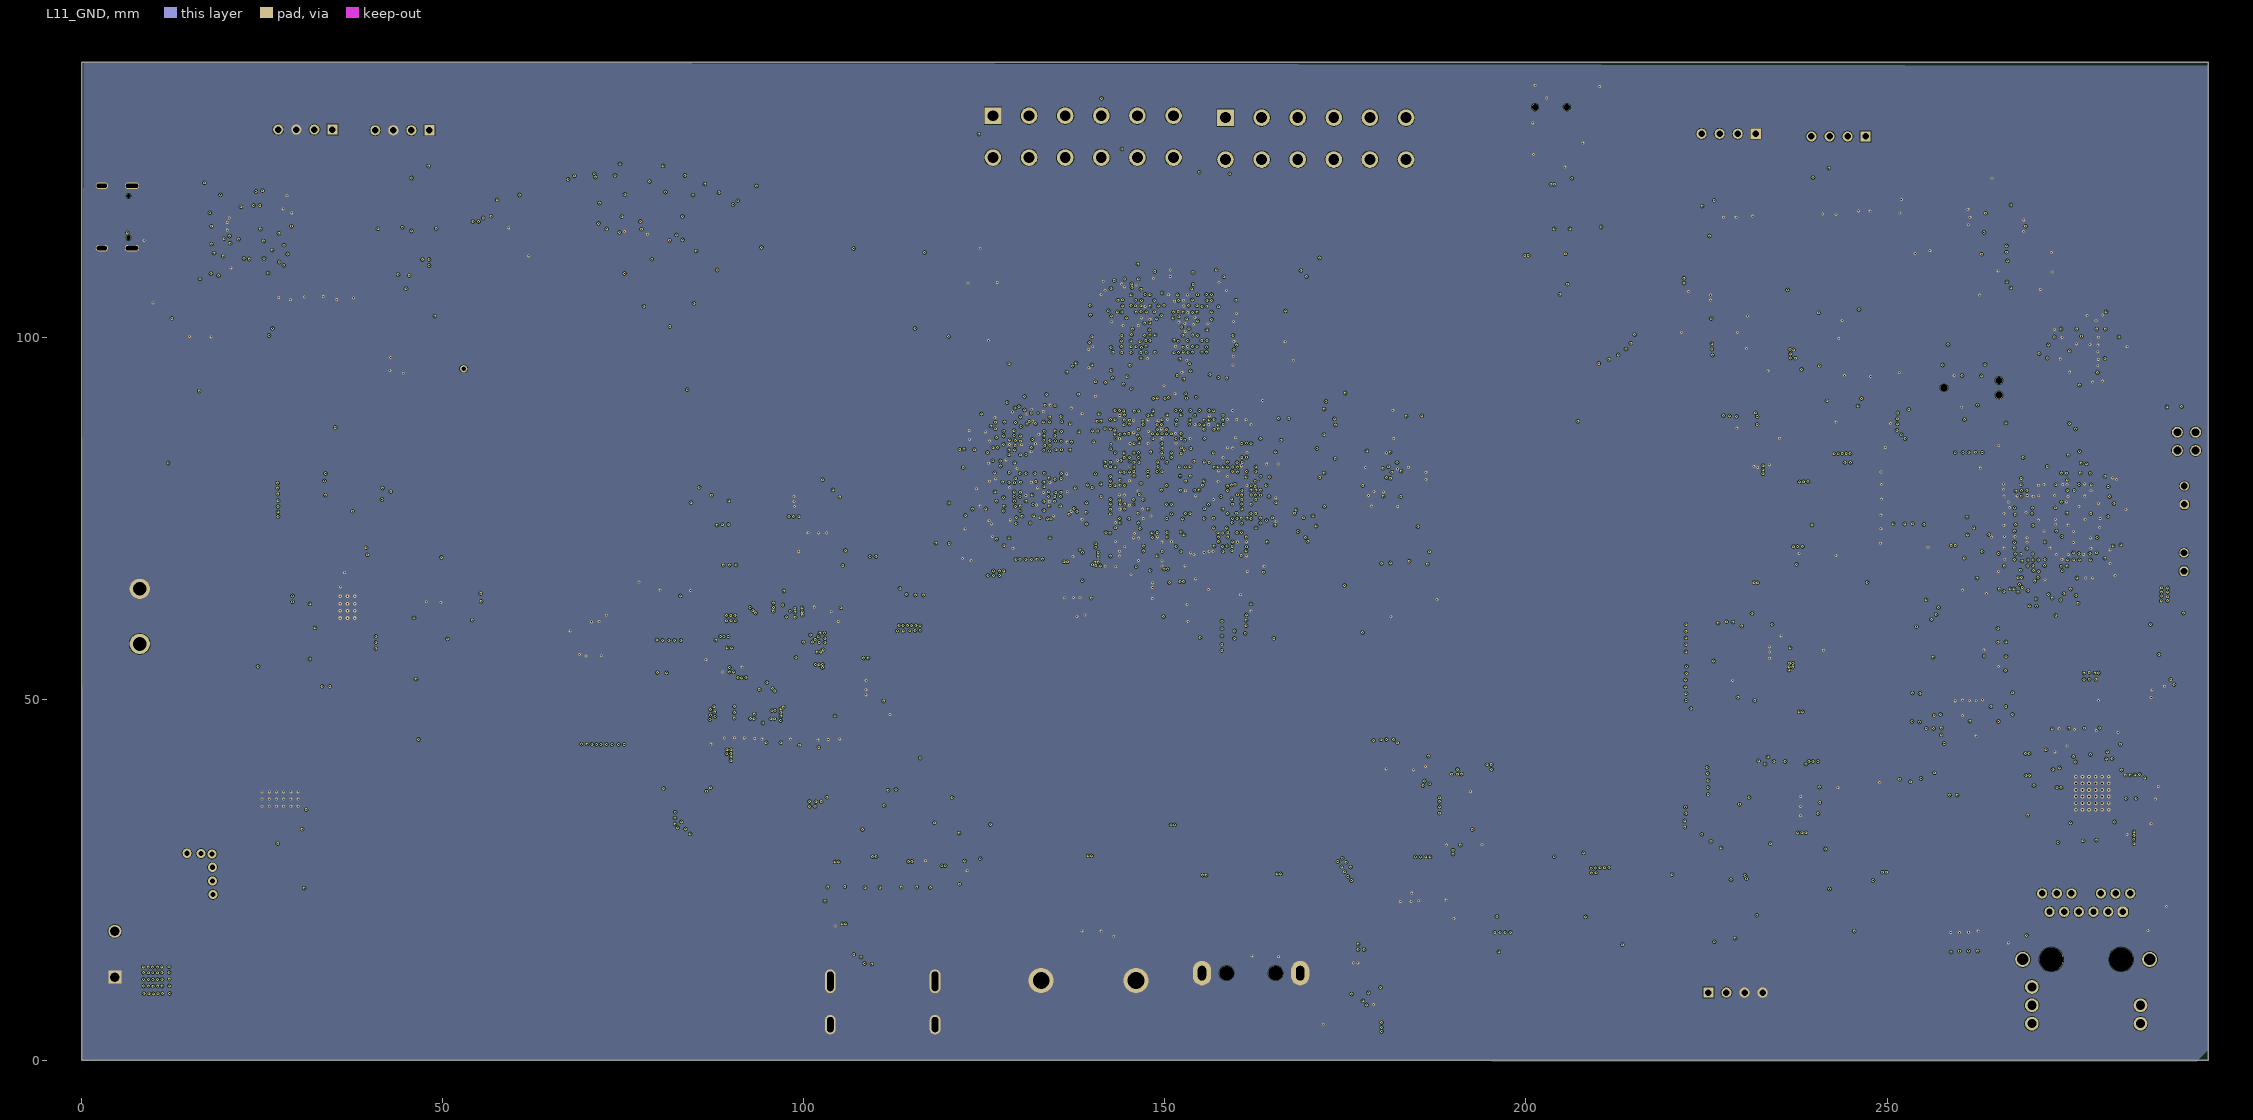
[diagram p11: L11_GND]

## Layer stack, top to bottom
Top Layer 1 _Signal: signal copper 0.0351
Prepreg.: prepreg 0.0864, 2313 RC58% 4.09mil, Dk 4.31
L2_GND: signal copper 0.03
Core: core 0.13, 0.13mm 1/1OZ without copper, Dk 4.03
L3_Signals: signal copper 0.03
Dielectric 6: prepreg 0.0889, 1080 RC69% 3.39mil, Dk 4.31
Dielectric 2: prepreg 0.0889, 080 RC69% 3.39mil, Dk 4.31
L4_GND: signal copper 0.03
Core.: core 0.13, 0.075mm 1/1OZ without copper, Dk 4.03
L5_POWER: signal copper 0.03
Prepreg 1: prepreg 0.0351, PP-001, Dk 3.92
Dielectric 1: prepreg 0.05, PP-001, Dk 3.92
Prepreg 2: prepreg 0.0196, PP-001, Dk 3.92
L6_Signals: signal copper 0.035
Core1: core 0.1501, Core-015, Dk 4.35
L7_GND: signal copper 0.035
Prepreg1: prepreg 0.0196, PP-001, Dk 3.92
Dielectric 3: prepreg 0.05, PP-001, Dk 3.92
Prepreg2: prepreg 0.0351, PP-001, Dk 3.92
L8_Signals: signal copper 0.03
Core 2: core 0.13, 0.075mm 1/1OZ without copper, Dk 4.03
L9_GND: signal copper 0.03
Prepreg11: prepreg 0.0889, 080 RC69% 3.39mil, Dk 4.31
Prepreg: prepreg 0.0889, 1080 RC69% 3.39mil, Dk 4.31
L10_POWER: signal copper 0.03
Coer: core 0.13, 0.13mm 1/1OZ without copper, Dk 4.03
L11_GND: signal copper 0.03
Dielectric 13: prepreg 0.0864, 2313 RC58% 4.09mil, Dk 4.31
Bottom Layer_Signals: signal copper 0.0351

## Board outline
0,0 294.513,0 294.513,138.176 0,138.176

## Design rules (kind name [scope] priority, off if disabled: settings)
Clearance [All] p1: gap=0.084 ignorepadtopadclearanceinfootprint=TRUE
ComponentClearance [InComponent('No Component') And OnLayer('Top Layer 1') vs InComponent('No Component') And OnLayer('Top Layer 1')] p1: gap=0.102 collisioncheckmode=3 verticalgap=0.102 showdistances=FALSE
DiffPairsRouting MDI [InDifferentialPairClass('MDI')] p1: maxlimit=0.229 minlimit=0.127 mostfreqgap=0.203 toplayer_mingap=0.229 toplayer_prefgap=0.229 toplayer_minwidth=0.111 toplayer_maxwidth=0.111 toplayer_prefwidth=0.111 midlayer1_maxgap=0.127 midlayer1_prefgap=0.127 midlayer1_minwidth=0.048 midlayer1_maxwidth=0.048 midlayer1_prefwidth=0.048 midlayer2_mingap=0.203 midlayer2_maxgap=0.203 midlayer2_minwidth=0.092 midlayer2_maxwidth=0.092 midlayer2_prefwidth=0.092 midlayer3_maxgap=0.127 midlayer3_prefgap=0.127 midlayer3_minwidth=0.064 midlayer3_maxwidth=0.064 midlayer3_prefwidth=0.064 midlayer4_mingap=0.203 midlayer4_maxgap=0.203 midlayer4_minwidth=0.089 midlayer4_maxwidth=0.089 midlayer4_prefwidth=0.089 midlayer5_mingap=0.203 midlayer5_maxgap=0.203 midlayer5_minwidth=0.089 midlayer5_maxwidth=0.089 midlayer5_prefwidth=0.089 midlayer6_mingap=0.203 midlayer6_maxgap=0.203 midlayer6_minwidth=0.089 midlayer6_maxwidth=0.089 midlayer6_prefwidth=0.089 midlayer7_mingap=0.203 midlayer7_maxgap=0.203 midlayer7_minwidth=0.089 midlayer7_maxwidth=0.089 midlayer7_prefwidth=0.089 midlayer8_maxgap=0.127 midlayer8_prefgap=0.127 midlayer8_minwidth=0.064 midlayer8_maxwidth=0.064 midlayer8_prefwidth=0.064 midlayer9_mingap=0.203 midlayer9_maxgap=0.203 midlayer9_minwidth=0.092 midlayer9_maxwidth=0.092 midlayer9_prefwidth=0.092 midlayer10_maxgap=0.127 midlayer10_prefgap=0.127 midlayer10_minwidth=0.048 midlayer10_maxwidth=0.048 midlayer10_prefwidth=0.048 bottomlayer_mingap=0.229 bottomlayer_prefgap=0.229 bottomlayer_minwidth=0.111 bottomlayer_maxwidth=0.111 bottomlayer_prefwidth=0.111 impedanceprofiledriven=TRUE impedanceprofileid={5E086DEA-4BCF-47A0-B150-B360DAA3B6F5} impedanceprofilevalue=100.000000 maxuncoupledlength=12.7
DiffPairsRouting RAM_80_DIFF [All] p2: maxlimit=0.152 minlimit=0.102 mostfreqgap=0.127 toplayer_mingap=0.152 toplayer_prefgap=0.152 toplayer_minwidth=0.161 toplayer_maxwidth=0.161 toplayer_prefwidth=0.161 midlayer1_mingap=0.127 midlayer1_maxgap=0.127 midlayer1_minwidth=0.092 midlayer1_maxwidth=0.092 midlayer1_prefwidth=0.092 midlayer2_maxgap=0.102 midlayer2_prefgap=0.102 midlayer2_minwidth=0.116 midlayer2_maxwidth=0.116 midlayer2_prefwidth=0.116 midlayer3_maxgap=0.102 midlayer3_prefgap=0.102 midlayer3_minwidth=0.115 midlayer3_maxwidth=0.115 midlayer3_prefwidth=0.115 midlayer4_mingap=0.152 midlayer4_prefgap=0.152 midlayer4_minwidth=0.115 midlayer4_maxwidth=0.115 midlayer4_prefwidth=0.115 midlayer5_mingap=0.112 midlayer5_maxgap=0.112 midlayer5_prefgap=0.112 midlayer5_minwidth=0.119 midlayer5_maxwidth=0.119 midlayer5_prefwidth=0.119 midlayer6_mingap=0.112 midlayer6_maxgap=0.112 midlayer6_prefgap=0.112 midlayer6_minwidth=0.119 midlayer6_maxwidth=0.119 midlayer6_prefwidth=0.119 midlayer7_mingap=0.152 midlayer7_prefgap=0.152 midlayer7_minwidth=0.115 midlayer7_maxwidth=0.115 midlayer7_prefwidth=0.115 midlayer8_maxgap=0.102 midlayer8_prefgap=0.102 midlayer8_minwidth=0.115 midlayer8_maxwidth=0.115 midlayer8_prefwidth=0.115 midlayer9_maxgap=0.102 midlayer9_prefgap=0.102 midlayer9_minwidth=0.116 midlayer9_maxwidth=0.116 midlayer9_prefwidth=0.116 midlayer10_mingap=0.127 midlayer10_maxgap=0.127 midlayer10_minwidth=0.092 midlayer10_maxwidth=0.092 midlayer10_prefwidth=0.092 bottomlayer_mingap=0.152 bottomlayer_prefgap=0.152 bottomlayer_minwidth=0.161 bottomlayer_maxwidth=0.161 bottomlayer_prefwidth=0.161 impedanceprofiledriven=TRUE impedanceprofileid={1387789D-10FC-4748-9014-9855CEFA5671} impedanceprofilevalue=80.000000 maxuncoupledlength=12.7
DiffPairsRouting HDMI [InDifferentialPairClass('HDMI_100')] p3: maxlimit=0.229 minlimit=0.127 mostfreqgap=0.203 toplayer_mingap=0.229 toplayer_prefgap=0.229 toplayer_minwidth=0.111 toplayer_maxwidth=0.111 toplayer_prefwidth=0.111 midlayer1_maxgap=0.127 midlayer1_prefgap=0.127 midlayer1_minwidth=0.048 midlayer1_maxwidth=0.048 midlayer1_prefwidth=0.048 midlayer2_mingap=0.203 midlayer2_maxgap=0.203 midlayer2_minwidth=0.092 midlayer2_maxwidth=0.092 midlayer2_prefwidth=0.092 midlayer3_maxgap=0.127 midlayer3_prefgap=0.127 midlayer3_minwidth=0.064 midlayer3_maxwidth=0.064 midlayer3_prefwidth=0.064 midlayer4_mingap=0.203 midlayer4_maxgap=0.203 midlayer4_minwidth=0.089 midlayer4_maxwidth=0.089 midlayer4_prefwidth=0.089 midlayer5_mingap=0.203 midlayer5_maxgap=0.203 midlayer5_minwidth=0.089 midlayer5_maxwidth=0.089 midlayer5_prefwidth=0.089 midlayer6_mingap=0.203 midlayer6_maxgap=0.203 midlayer6_minwidth=0.089 midlayer6_maxwidth=0.089 midlayer6_prefwidth=0.089 midlayer7_mingap=0.203 midlayer7_maxgap=0.203 midlayer7_minwidth=0.089 midlayer7_maxwidth=0.089 midlayer7_prefwidth=0.089 midlayer8_maxgap=0.127 midlayer8_prefgap=0.127 midlayer8_minwidth=0.064 midlayer8_maxwidth=0.064 midlayer8_prefwidth=0.064 midlayer9_mingap=0.203 midlayer9_maxgap=0.203 midlayer9_minwidth=0.092 midlayer9_maxwidth=0.092 midlayer9_prefwidth=0.092 midlayer10_maxgap=0.127 midlayer10_prefgap=0.127 midlayer10_minwidth=0.048 midlayer10_maxwidth=0.048 midlayer10_prefwidth=0.048 bottomlayer_mingap=0.229 bottomlayer_prefgap=0.229 bottomlayer_minwidth=0.111 bottomlayer_maxwidth=0.111 bottomlayer_prefwidth=0.111 impedanceprofiledriven=TRUE impedanceprofileid={5E086DEA-4BCF-47A0-B150-B360DAA3B6F5} impedanceprofilevalue=100.000000 maxuncoupledlength=12.7
DiffPairsRouting 90Ohms [InDifferentialPairClass('90Ohm')] p4: maxlimit=0.191 minlimit=0.127 mostfreqgap=0.191 toplayer_mingap=0.178 toplayer_maxgap=0.178 toplayer_prefgap=0.178 toplayer_minwidth=0.131 toplayer_maxwidth=0.131 toplayer_prefwidth=0.131 midlayer1_maxgap=0.127 midlayer1_prefgap=0.127 midlayer1_minwidth=0.067 midlayer1_maxwidth=0.067 midlayer1_prefwidth=0.067 midlayer2_mingap=0.191 midlayer2_minwidth=0.118 midlayer2_maxwidth=0.118 midlayer2_prefwidth=0.118 midlayer3_maxgap=0.127 midlayer3_prefgap=0.127 midlayer3_minwidth=0.092 midlayer3_maxwidth=0.092 midlayer3_prefwidth=0.092 midlayer4_mingap=0.191 midlayer4_minwidth=0.094 midlayer4_maxwidth=0.094 midlayer4_prefwidth=0.094 midlayer5_mingap=0.191 midlayer5_minwidth=0.114 midlayer5_maxwidth=0.114 midlayer5_prefwidth=0.114 midlayer6_mingap=0.191 midlayer6_minwidth=0.114 midlayer6_maxwidth=0.114 midlayer6_prefwidth=0.114 midlayer7_mingap=0.191 midlayer7_minwidth=0.094 midlayer7_maxwidth=0.094 midlayer7_prefwidth=0.094 midlayer8_maxgap=0.127 midlayer8_prefgap=0.127 midlayer8_minwidth=0.092 midlayer8_maxwidth=0.092 midlayer8_prefwidth=0.092 midlayer9_mingap=0.191 midlayer9_minwidth=0.118 midlayer9_maxwidth=0.118 midlayer9_prefwidth=0.118 midlayer10_maxgap=0.127 midlayer10_prefgap=0.127 midlayer10_minwidth=0.067 midlayer10_maxwidth=0.067 midlayer10_prefwidth=0.067 bottomlayer_mingap=0.178 bottomlayer_maxgap=0.178 bottomlayer_prefgap=0.178 bottomlayer_minwidth=0.131 bottomlayer_maxwidth=0.131 bottomlayer_prefwidth=0.131 impedanceprofiledriven=TRUE impedanceprofileid={9723B2C0-F0BF-43FB-8C25-FD1EE65D185F} impedanceprofilevalue=90.000000 maxuncoupledlength=12.7
DiffPairsRouting 100R [InDifferentialPairClass('100R_VS')] p5: maxlimit=0.229 minlimit=0.127 mostfreqgap=0.203 toplayer_mingap=0.229 toplayer_prefgap=0.229 toplayer_minwidth=0.111 toplayer_maxwidth=0.111 toplayer_prefwidth=0.111 midlayer1_maxgap=0.127 midlayer1_prefgap=0.127 midlayer1_minwidth=0.048 midlayer1_maxwidth=0.048 midlayer1_prefwidth=0.048 midlayer2_mingap=0.203 midlayer2_maxgap=0.203 midlayer2_minwidth=0.092 midlayer2_maxwidth=0.092 midlayer2_prefwidth=0.092 midlayer3_maxgap=0.127 midlayer3_prefgap=0.127 midlayer3_minwidth=0.064 midlayer3_maxwidth=0.064 midlayer3_prefwidth=0.064 midlayer4_mingap=0.203 midlayer4_maxgap=0.203 midlayer4_minwidth=0.089 midlayer4_maxwidth=0.089 midlayer4_prefwidth=0.089 midlayer5_mingap=0.203 midlayer5_maxgap=0.203 midlayer5_minwidth=0.089 midlayer5_maxwidth=0.089 midlayer5_prefwidth=0.089 midlayer6_mingap=0.203 midlayer6_maxgap=0.203 midlayer6_minwidth=0.089 midlayer6_maxwidth=0.089 midlayer6_prefwidth=0.089 midlayer7_mingap=0.203 midlayer7_maxgap=0.203 midlayer7_minwidth=0.089 midlayer7_maxwidth=0.089 midlayer7_prefwidth=0.089 midlayer8_maxgap=0.127 midlayer8_prefgap=0.127 midlayer8_minwidth=0.064 midlayer8_maxwidth=0.064 midlayer8_prefwidth=0.064 midlayer9_mingap=0.203 midlayer9_maxgap=0.203 midlayer9_minwidth=0.092 midlayer9_maxwidth=0.092 midlayer9_prefwidth=0.092 midlayer10_maxgap=0.127 midlayer10_prefgap=0.127 midlayer10_minwidth=0.048 midlayer10_maxwidth=0.048 midlayer10_prefwidth=0.048 bottomlayer_mingap=0.229 bottomlayer_prefgap=0.229 bottomlayer_minwidth=0.111 bottomlayer_maxwidth=0.111 bottomlayer_prefwidth=0.111 impedanceprofiledriven=TRUE impedanceprofileid={5E086DEA-4BCF-47A0-B150-B360DAA3B6F5} impedanceprofilevalue=100.000000 maxuncoupledlength=12.7
DiffPairsRouting RAM_DIFF [InDifferentialPairClass('RAM_80')] p6: maxlimit=0.152 minlimit=0.102 mostfreqgap=0.127 toplayer_mingap=0.152 toplayer_prefgap=0.152 toplayer_minwidth=0.161 toplayer_maxwidth=0.161 toplayer_prefwidth=0.161 midlayer1_mingap=0.127 midlayer1_maxgap=0.127 midlayer1_minwidth=0.092 midlayer1_maxwidth=0.092 midlayer1_prefwidth=0.092 midlayer2_maxgap=0.102 midlayer2_prefgap=0.102 midlayer2_minwidth=0.116 midlayer2_maxwidth=0.116 midlayer2_prefwidth=0.116 midlayer3_maxgap=0.102 midlayer3_prefgap=0.102 midlayer3_minwidth=0.115 midlayer3_maxwidth=0.115 midlayer3_prefwidth=0.115 midlayer4_mingap=0.152 midlayer4_prefgap=0.152 midlayer4_minwidth=0.115 midlayer4_maxwidth=0.115 midlayer4_prefwidth=0.115 midlayer5_mingap=0.112 midlayer5_maxgap=0.112 midlayer5_prefgap=0.112 midlayer5_minwidth=0.119 midlayer5_maxwidth=0.119 midlayer5_prefwidth=0.119 midlayer6_mingap=0.112 midlayer6_maxgap=0.112 midlayer6_prefgap=0.112 midlayer6_minwidth=0.119 midlayer6_maxwidth=0.119 midlayer6_prefwidth=0.119 midlayer7_mingap=0.152 midlayer7_prefgap=0.152 midlayer7_minwidth=0.115 midlayer7_maxwidth=0.115 midlayer7_prefwidth=0.115 midlayer8_maxgap=0.102 midlayer8_prefgap=0.102 midlayer8_minwidth=0.115 midlayer8_maxwidth=0.115 midlayer8_prefwidth=0.115 midlayer9_maxgap=0.102 midlayer9_prefgap=0.102 midlayer9_minwidth=0.116 midlayer9_maxwidth=0.116 midlayer9_prefwidth=0.116 midlayer10_mingap=0.127 midlayer10_maxgap=0.127 midlayer10_minwidth=0.092 midlayer10_maxwidth=0.092 midlayer10_prefwidth=0.092 bottomlayer_mingap=0.152 bottomlayer_prefgap=0.152 bottomlayer_minwidth=0.161 bottomlayer_maxwidth=0.161 bottomlayer_prefwidth=0.161 impedanceprofiledriven=TRUE impedanceprofileid={1387789D-10FC-4748-9014-9855CEFA5671} impedanceprofilevalue=80.000000 maxuncoupledlength=12.7
DiffPairsRouting DBG_UART [InDifferentialPairClass('DBG_UART')] p7: maxlimit=0.191 minlimit=0.127 mostfreqgap=0.191 toplayer_mingap=0.178 toplayer_maxgap=0.178 toplayer_prefgap=0.178 toplayer_minwidth=0.131 toplayer_maxwidth=0.131 toplayer_prefwidth=0.131 midlayer1_maxgap=0.127 midlayer1_prefgap=0.127 midlayer1_minwidth=0.067 midlayer1_maxwidth=0.067 midlayer1_prefwidth=0.067 midlayer2_mingap=0.191 midlayer2_minwidth=0.118 midlayer2_maxwidth=0.118 midlayer2_prefwidth=0.118 midlayer3_maxgap=0.127 midlayer3_prefgap=0.127 midlayer3_minwidth=0.092 midlayer3_maxwidth=0.092 midlayer3_prefwidth=0.092 midlayer4_mingap=0.191 midlayer4_minwidth=0.094 midlayer4_maxwidth=0.094 midlayer4_prefwidth=0.094 midlayer5_mingap=0.191 midlayer5_minwidth=0.114 midlayer5_maxwidth=0.114 midlayer5_prefwidth=0.114 midlayer6_mingap=0.191 midlayer6_minwidth=0.114 midlayer6_maxwidth=0.114 midlayer6_prefwidth=0.114 midlayer7_mingap=0.191 midlayer7_minwidth=0.094 midlayer7_maxwidth=0.094 midlayer7_prefwidth=0.094 midlayer8_maxgap=0.127 midlayer8_prefgap=0.127 midlayer8_minwidth=0.092 midlayer8_maxwidth=0.092 midlayer8_prefwidth=0.092 midlayer9_mingap=0.191 midlayer9_minwidth=0.118 midlayer9_maxwidth=0.118 midlayer9_prefwidth=0.118 midlayer10_maxgap=0.127 midlayer10_prefgap=0.127 midlayer10_minwidth=0.067 midlayer10_maxwidth=0.067 midlayer10_prefwidth=0.067 bottomlayer_mingap=0.178 bottomlayer_maxgap=0.178 bottomlayer_prefgap=0.178 bottomlayer_minwidth=0.131 bottomlayer_maxwidth=0.131 bottomlayer_prefwidth=0.131 impedanceprofiledriven=TRUE impedanceprofileid={9723B2C0-F0BF-43FB-8C25-FD1EE65D185F} impedanceprofilevalue=90.000000 maxuncoupledlength=12.7
DiffPairsRouting RP_USB_Diff [InDifferentialPairClass('RP_USB')] p8: maxlimit=0.191 minlimit=0.127 mostfreqgap=0.191 toplayer_mingap=0.178 toplayer_maxgap=0.178 toplayer_prefgap=0.178 toplayer_minwidth=0.131 toplayer_maxwidth=0.131 toplayer_prefwidth=0.131 midlayer1_maxgap=0.127 midlayer1_prefgap=0.127 midlayer1_minwidth=0.067 midlayer1_maxwidth=0.067 midlayer1_prefwidth=0.067 midlayer2_mingap=0.191 midlayer2_minwidth=0.118 midlayer2_maxwidth=0.118 midlayer2_prefwidth=0.118 midlayer3_maxgap=0.127 midlayer3_prefgap=0.127 midlayer3_minwidth=0.092 midlayer3_maxwidth=0.092 midlayer3_prefwidth=0.092 midlayer4_mingap=0.191 midlayer4_minwidth=0.094 midlayer4_maxwidth=0.094 midlayer4_prefwidth=0.094 midlayer5_mingap=0.191 midlayer5_minwidth=0.114 midlayer5_maxwidth=0.114 midlayer5_prefwidth=0.114 midlayer6_mingap=0.191 midlayer6_minwidth=0.114 midlayer6_maxwidth=0.114 midlayer6_prefwidth=0.114 midlayer7_mingap=0.191 midlayer7_minwidth=0.094 midlayer7_maxwidth=0.094 midlayer7_prefwidth=0.094 midlayer8_maxgap=0.127 midlayer8_prefgap=0.127 midlayer8_minwidth=0.092 midlayer8_maxwidth=0.092 midlayer8_prefwidth=0.092 midlayer9_mingap=0.191 midlayer9_minwidth=0.118 midlayer9_maxwidth=0.118 midlayer9_prefwidth=0.118 midlayer10_maxgap=0.127 midlayer10_prefgap=0.127 midlayer10_minwidth=0.067 midlayer10_maxwidth=0.067 midlayer10_prefwidth=0.067 bottomlayer_mingap=0.178 bottomlayer_maxgap=0.178 bottomlayer_prefgap=0.178 bottomlayer_minwidth=0.131 bottomlayer_maxwidth=0.131 bottomlayer_prefwidth=0.131 impedanceprofiledriven=TRUE impedanceprofileid={9723B2C0-F0BF-43FB-8C25-FD1EE65D185F} impedanceprofilevalue=90.000000 maxuncoupledlength=12.7
DiffPairsRouting [All] p9: maxlimit=0.254 minlimit=0.254 mostfreqgap=0.254 toplayer_minwidth=0.381 toplayer_maxwidth=0.381 toplayer_prefwidth=0.381 midlayer1_minwidth=0.381 midlayer1_maxwidth=0.381 midlayer1_prefwidth=0.381 midlayer2_minwidth=0.381 midlayer2_maxwidth=0.381 midlayer2_prefwidth=0.381 midlayer3_minwidth=0.381 midlayer3_maxwidth=0.381 midlayer3_prefwidth=0.381 midlayer4_minwidth=0.381 midlayer4_maxwidth=0.381 midlayer4_prefwidth=0.381 midlayer5_minwidth=0.381 midlayer5_maxwidth=0.381 midlayer5_prefwidth=0.381 midlayer6_minwidth=0.381 midlayer6_maxwidth=0.381 midlayer6_prefwidth=0.381 midlayer7_minwidth=0.381 midlayer7_maxwidth=0.381 midlayer7_prefwidth=0.381 midlayer8_minwidth=0.381 midlayer8_maxwidth=0.381 midlayer8_prefwidth=0.381 midlayer9_minwidth=0.381 midlayer9_maxwidth=0.381 midlayer9_prefwidth=0.381 midlayer10_minwidth=0.381 midlayer10_maxwidth=0.381 midlayer10_prefwidth=0.381 bottomlayer_minwidth=0.381 bottomlayer_maxwidth=0.381 bottomlayer_prefwidth=0.381 maxuncoupledlength=12.7
HoleToHoleClearance [All] p1: gap=0.089 allowstackedmicrovias=TRUE
MatchedLengths "Schematic Matched Net Lengths_6" [InNet('P28.A_P')] p1: tolerance=1.016 checknetsindiffpair=TRUE checkdiffpairvsdiffpair=FALSE checkxsignals=FALSE checkothers=FALSE
MatchedLengths DP_RGMII_RX [InNetClass('DP_50Ohms_RX_')] p2: tolerance=5.08 checknetsindiffpair=FALSE checkdiffpairvsdiffpair=TRUE checkxsignals=TRUE checkothers=TRUE
MatchedLengths DP_RGMII_TX [InNetClass('DP_50Ohms_TX')] p3: tolerance=25.4 checknetsindiffpair=FALSE checkdiffpairvsdiffpair=TRUE checkxsignals=TRUE checkothers=TRUE
MatchedLengths RAM_2_CH1_D [InxSignalClass('RAM2_CH1_D')] p4: tolerance=2.54 checknetsindiffpair=FALSE checkdiffpairvsdiffpair=TRUE checkxsignals=TRUE checkothers=TRUE usedelayunits=TRUE delaytolerance=100.000000
MatchedLengths RAM_2_CH0_C [InxSignalClass('RAM2_CH0_C')] p5: tolerance=25.4 checknetsindiffpair=FALSE checkdiffpairvsdiffpair=TRUE checkxsignals=TRUE checkothers=TRUE usedelayunits=TRUE delaytolerance=100.000000
MatchedLengths RAM_CH0_B [InxSignalClass('RAM1_CH0_B')] p6: tolerance=25.4 checknetsindiffpair=FALSE checkdiffpairvsdiffpair=TRUE checkxsignals=TRUE checkothers=TRUE usedelayunits=TRUE delaytolerance=100.000000
MatchedLengths RAM_CH0 [InxSignalClass('RAM_1_CH0_A')] p7: tolerance=0.254 checknetsindiffpair=FALSE checkdiffpairvsdiffpair=TRUE checkxsignals=TRUE checkothers=TRUE usedelayunits=TRUE delaytolerance=100.000000
MatchedLengths RAM_80 [InDifferentialPairClass('RAM_80')] p8: tolerance=25.4 checknetsindiffpair=FALSE checkdiffpairvsdiffpair=TRUE checkxsignals=TRUE checkothers=TRUE usedelayunits=TRUE delaytolerance=60.000000
MatchedLengths "Schematic Matched Net Lengths_5" [InNetClass('RGMII_TX')] p9: tolerance=2.54 checknetsindiffpair=FALSE checkdiffpairvsdiffpair=TRUE checkxsignals=TRUE checkothers=TRUE
MatchedLengths "Schematic Matched Net Lengths_2" [InNetClass('RGMII_RX')] p10: tolerance=2.54 checknetsindiffpair=FALSE checkdiffpairvsdiffpair=TRUE checkxsignals=TRUE checkothers=TRUE
MatchedLengths MIDI [InNetClass('EMMC_9696')] p11: tolerance=2.54 checknetsindiffpair=FALSE checkdiffpairvsdiffpair=TRUE checkxsignals=TRUE checkothers=TRUE
MatchedLengths 9696_EMMC_1 [InNetClass('EMMC_9696')] p12: tolerance=5.08 checknetsindiffpair=FALSE checkdiffpairvsdiffpair=TRUE checkxsignals=TRUE checkothers=TRUE
MatchedLengths QSPI_9696_1 [InNetClass('QSPI')] p13: tolerance=0.508 checknetsindiffpair=FALSE checkdiffpairvsdiffpair=TRUE checkxsignals=TRUE checkothers=TRUE
MatchedLengths EMMC_1 [InNetClass('EMMC_50')] p14: tolerance=2 checknetsindiffpair=FALSE checkdiffpairvsdiffpair=TRUE checkxsignals=TRUE checkothers=TRUE
MatchedLengths "Schematic Matched Net Lengths" [InNet('PCIE_RX_P')] p15: tolerance=0.127 checknetsindiffpair=TRUE checkdiffpairvsdiffpair=FALSE checkxsignals=FALSE checkothers=FALSE
MatchedLengths "Schematic Matched Net Lengths_3" [InNetClass('QSPI')] p16: tolerance=2.54 checknetsindiffpair=FALSE checkdiffpairvsdiffpair=TRUE checkxsignals=TRUE checkothers=TRUE
MaxMinImpedance "Schematic Impedance Constraint_5" [InNetClass('RGMII_RX')] p1: minimum=47.00 maximum=53.00
MaxMinImpedance "Schematic Impedance Constraint_4" [InNetClass('RGMII_TX')] p2: minimum=47.00 maximum=53.00
MaxMinImpedance "Schematic Impedance Constraint" [InNetClass('EMMC_9696')] p3: minimum=47.00 maximum=53.00
MaxMinImpedance "Schematic Impedance Constraint_3" [InNetClass('HiSpeed')] p4: minimum=95.00 maximum=105.0
MaxMinImpedance "Schematic Impedance Constraint_2" [InNetClass('MDI')] p5: minimum=95.00 maximum=105.0
MaxMinImpedance "Schematic Impedance Constraint_1" [InNetClass('QSPI')] p6: minimum=47.00 maximum=53.00
MaximumViaCount "Schematic Maximum Via Count Constraint_3" [InDifferentialPairClass('Clock')] p1: limit=2
MaximumViaCount "Schematic Maximum Via Count Constraint" [InNetClass('MDI')] p2: limit=1
MinimumSolderMaskSliver [All] p1: minsoldermaskwidth=0.089
PlaneConnect [All] p1: planeconnectstyle=Direct reliefexpansion=0.508 reliefentries=2 reliefconductorwidth=0.254 reliefairgap=0.254
PolygonConnect [All] p1: connectstyle=Direct reliefconductorwidth=0.254 reliefentries=4 polygonreliefangle="90 Angle" airgapwidth=0.254
RoutingTopology "Schematic Routing Topology_3" [InNetClass('RGMII_RX')] p1: topology=Daisy_Simple
RoutingTopology "Schematic Routing Topology_2" [InNetClass('RGMII_TX')] p2: topology=Daisy_Simple
RoutingTopology "Schematic Routing Topology_1" [InNetClass('EMMC_9696')] p3: topology=Daisy_Simple
RoutingTopology "Schematic Routing Topology" [InNetClass('QSPI')] p4: topology=Daisy_Simple
RoutingTopology [All] p5: topology=Shortest
RoutingVias [All] p1: holewidth=0.2 width=0.4 viastyle="Through Hole" minholewidth=0.2 minwidth=0.4 maxholewidth=0.2 maxwidth=0.4
SilkToSilkClearance [All] p1: silktosilkclearance=0.089
SilkToSolderMaskClearance [IsPad] p1: minsilkscreentomaskgap=0.089 clearancetoexposedcopper=TRUE
SolderMaskExpansion SolderMaskExpansion_1 [All] p1: expansion=0.102 istentingtop=FALSE
SolderMaskExpansion "All Vias Tented" [IsVia] p2: expansion=0.102 istentingtop=TRUE
SupplyNets "Schematic Supply Nets_6" [InNet('VDD_NPU_S0')] p1: voltage=0.000
SupplyNets "Schematic Supply Nets" [InNet('VDDQ_DDR_CK')] p2: voltage=0.000
SupplyNets "Schematic Supply Nets_7" [InNet('12V')] p3: voltage=0.000
SupplyNets "Schematic Supply Nets_48" [InNet('+24V')] p4: voltage=0.000
SupplyNets "Schematic Supply Nets_39" [InNet('VCC_2V0_PLD0_S3')] p5: voltage=0.000
SupplyNets "Schematic Supply Nets_29" [InNet('2V5_DP')] p6: voltage=0.000
SupplyNets "Schematic Supply Nets_26" [InNet('RP_1V1')] p7: voltage=0.000
SupplyNets "Schematic Supply Nets_25" [InNet('1V8_DP')] p8: voltage=0.000
SupplyNets "Schematic Supply Nets_24" [InNet('RP_VBUS')] p9: voltage=0.000
SupplyNets "Schematic Supply Nets_19" [InNet('1V0_VSC')] p10: voltage=0.000
SupplyNets "Schematic Supply Nets_18" [InNet('2V5_VSC')] p11: voltage=0.000
SupplyNets "Schematic Supply Nets_10" [InNet('VCC5V0_USB20_HOST')] p12: voltage=0.000
SupplyNets "Schematic Supply Nets_75" [InNet('VDDQ_DRAM')] p13: voltage=0.000
SupplyNets "Schematic Supply Nets_73" [InNet('VCC5V_HDMI_TX0')] p14: voltage=0.000
SupplyNets "Schematic Supply Nets_72" [InNet('VDD_GPU_S0')] p15: voltage=0.000
SupplyNets "Schematic Supply Nets_70" [InNet('1V2')] p16: voltage=0.000
SupplyNets "Schematic Supply Nets_69" [InNet('NLDO4')] p17: voltage=0.000
SupplyNets "Schematic Supply Nets_68" [InNet('SHIELD_GND_MNG')] p18: voltage=0.000
SupplyNets "Schematic Supply Nets_64" [InNet('NLDO3')] p19: voltage=0.000
SupplyNets "Schematic Supply Nets_62" [InNet('VCC14')] p20: voltage=0.000
SupplyNets "Schematic Supply Nets_60" [InNet('VCC_3V3_S0')] p21: voltage=0.000
SupplyNets "Schematic Supply Nets_59" [InNet('1V1')] p22: voltage=0.000
SupplyNets "Schematic Supply Nets_56" [InNet('VDD_CPU_BIG1_MEM_S0')] p23: voltage=0.000
SupplyNets "Schematic Supply Nets_53" [InNet('VCC_1V8_S0')] p24: voltage=0.000
SupplyNets "Schematic Supply Nets_52" [InNet('VCCA_1V8')] p25: voltage=0.000
SupplyNets "Schematic Supply Nets_50" [InNet('0V9')] p26: voltage=0.000
SupplyNets "Schematic Supply Nets_49" [InNet('VCC3V3_LCD')] p27: voltage=0.000
SupplyNets "Schematic Supply Nets_47" [InNet('VDD_DDR_S0')] p28: voltage=0.000
SupplyNets "Schematic Supply Nets_44" [InNet('NLDO5')] p29: voltage=0.000
SupplyNets "Schematic Supply Nets_43" [InNet('VDDA_1V2_S0')] p30: voltage=0.000
SupplyNets "Schematic Supply Nets_42" [InNet('VCCQ')] p31: voltage=0.000
SupplyNets "Schematic Supply Nets_38" [InNet('GND')] p32: voltage=0.000
SupplyNets "Schematic Supply Nets_37" [InNet('VDD2_DDR_CKE')] p33: voltage=0.000
SupplyNets "Schematic Supply Nets_36" [InNet('VDD_CPU_BIG1_S0')] p34: voltage=0.000
SupplyNets "Schematic Supply Nets_35" [InNet('NLDO1')] p35: voltage=0.000
SupplyNets "Schematic Supply Nets_34" [InNet('EMMC_VCC')] p36: voltage=0.000
SupplyNets "Schematic Supply Nets_32" [InNet('1V8')] p37: voltage=0.000
SupplyNets "Schematic Supply Nets_31" [InNet('VOUT6')] p38: voltage=0.000
SupplyNets "Schematic Supply Nets_28" [InNet('VCC5V0_FT232')] p39: voltage=0.000
SupplyNets "Schematic Supply Nets_27" [InNet('VDD_VDENC_S0')] p40: voltage=0.000
SupplyNets "Schematic Supply Nets_23" [InNet('2V5')] p41: voltage=0.000
SupplyNets "Schematic Supply Nets_22" [InNet('VCC_5V0')] p42: voltage=0.000
SupplyNets "Schematic Supply Nets_21" [InNet('3V3')] p43: voltage=0.000
SupplyNets "Schematic Supply Nets_20" [InNet('VCC3V3_FT232')] p44: voltage=0.000
SupplyNets "Schematic Supply Nets_17" [InNet('NLDO2')] p45: voltage=0.000
SupplyNets "Schematic Supply Nets_16" [InNet('VCC1')] p46: voltage=0.000
SupplyNets "Schematic Supply Nets_15" [InNet('VCC1V8_PMU_DDR_S3')] p47: voltage=0.000
SupplyNets "Schematic Supply Nets_14" [InNet('PLDO5')] p48: voltage=0.000
SupplyNets "Schematic Supply Nets_12" [InNet('VDD_CPU_LIT_S0')] p49: voltage=0.000
SupplyNets "Schematic Supply Nets_9" [InNet('5V')] p50: voltage=0.000
SupplyNets "Schematic Supply Nets_8" [InNet('VCC_2V0_PLDO_S3')] p51: voltage=0.000
SupplyNets "Schematic Supply Nets_5" [InNet('PLDO4')] p52: voltage=0.000
SupplyNets "Schematic Supply Nets_4" [InNet('VDD_LOG_S0')] p53: voltage=0.000
SupplyNets "Schematic Supply Nets_3" [InNet('VOUT9')] p54: voltage=0.000
SupplyNets "Schematic Supply Nets_2" [InNet('VCC_1V8_S3_PLDO6')] p55: voltage=0.000
SupplyNets "Schematic Supply Nets_1" [InNet('VDD_CPU_BIG0_S0')] p56: voltage=0.000
Width RK_50Ohms [InNetClass('RK_50OHM')] p1: maxlimit=1.27 minlimit=0.089 preferedwidth=0.106 toplayer_minwidth=0.132 toplayer_prefwidth=0.132 midlayer2_minwidth=0.113 midlayer2_prefwidth=0.113 midlayer3_minwidth=0.102 midlayer3_prefwidth=0.102 midlayer4_prefwidth=0.089 midlayer5_minwidth=0.106 midlayer6_minwidth=0.106 midlayer7_prefwidth=0.089 midlayer8_minwidth=0.102 midlayer8_prefwidth=0.102 midlayer9_minwidth=0.113 midlayer9_prefwidth=0.113 bottomlayer_minwidth=0.132 bottomlayer_prefwidth=0.132 impedanceprofiledriven=TRUE impedanceprofileid={3A7C7114-273F-42D4-9E86-C85CF69E2638} impedanceprofilevalue=50.000000 minimp=50.000000 maximp=50.000000 favimp=50.000000
Width RGMII_RX [InNetClass('RGMII_RX')] p2: maxlimit=0.254 minlimit=0.089 preferedwidth=0.106 toplayer_minwidth=0.132 toplayer_maxwidth=0.132 toplayer_prefwidth=0.132 midlayer2_minwidth=0.113 midlayer2_maxwidth=0.113 midlayer2_prefwidth=0.113 midlayer3_minwidth=0.102 midlayer3_maxwidth=0.102 midlayer3_prefwidth=0.102 midlayer4_maxwidth=0.089 midlayer4_prefwidth=0.089 midlayer5_minwidth=0.106 midlayer5_maxwidth=0.106 midlayer6_minwidth=0.106 midlayer6_maxwidth=0.106 midlayer7_maxwidth=0.089 midlayer7_prefwidth=0.089 midlayer8_minwidth=0.102 midlayer8_maxwidth=0.102 midlayer8_prefwidth=0.102 midlayer9_minwidth=0.113 midlayer9_maxwidth=0.113 midlayer9_prefwidth=0.113 bottomlayer_minwidth=0.132 bottomlayer_maxwidth=0.132 bottomlayer_prefwidth=0.132 impedanceprofiledriven=TRUE impedanceprofileid={3A7C7114-273F-42D4-9E86-C85CF69E2638} impedanceprofilevalue=50.000000 minimp=50.000000 maximp=50.000000 favimp=50.000000
Width RGMII_TX [InNetClass('RGMII_TX')] p3: maxlimit=0.254 minlimit=0.089 preferedwidth=0.106 toplayer_minwidth=0.132 toplayer_maxwidth=0.132 toplayer_prefwidth=0.132 midlayer2_minwidth=0.113 midlayer2_maxwidth=0.113 midlayer2_prefwidth=0.113 midlayer3_minwidth=0.102 midlayer3_maxwidth=0.102 midlayer3_prefwidth=0.102 midlayer4_maxwidth=0.089 midlayer4_prefwidth=0.089 midlayer5_minwidth=0.106 midlayer5_maxwidth=0.106 midlayer6_minwidth=0.106 midlayer6_maxwidth=0.106 midlayer7_maxwidth=0.089 midlayer7_prefwidth=0.089 midlayer8_minwidth=0.102 midlayer8_maxwidth=0.102 midlayer8_prefwidth=0.102 midlayer9_minwidth=0.113 midlayer9_maxwidth=0.113 midlayer9_prefwidth=0.113 bottomlayer_minwidth=0.132 bottomlayer_maxwidth=0.132 bottomlayer_prefwidth=0.132 impedanceprofiledriven=TRUE impedanceprofileid={3A7C7114-273F-42D4-9E86-C85CF69E2638} impedanceprofilevalue=50.000000 minimp=50.000000 maximp=50.000000 favimp=50.000000
Width 9696_EMMC [InNetClass('EMMC_9696')] p4: maxlimit=0.254 minlimit=0.089 preferedwidth=0.106 toplayer_minwidth=0.132 toplayer_maxwidth=0.132 toplayer_prefwidth=0.132 midlayer2_minwidth=0.113 midlayer2_maxwidth=0.113 midlayer2_prefwidth=0.113 midlayer3_minwidth=0.102 midlayer3_maxwidth=0.102 midlayer3_prefwidth=0.102 midlayer4_maxwidth=0.089 midlayer4_prefwidth=0.089 midlayer5_minwidth=0.106 midlayer5_maxwidth=0.106 midlayer6_minwidth=0.106 midlayer6_maxwidth=0.106 midlayer7_maxwidth=0.089 midlayer7_prefwidth=0.089 midlayer8_minwidth=0.102 midlayer8_maxwidth=0.102 midlayer8_prefwidth=0.102 midlayer9_minwidth=0.113 midlayer9_maxwidth=0.113 midlayer9_prefwidth=0.113 bottomlayer_minwidth=0.132 bottomlayer_maxwidth=0.132 bottomlayer_prefwidth=0.132 impedanceprofiledriven=TRUE impedanceprofileid={3A7C7114-273F-42D4-9E86-C85CF69E2638} impedanceprofilevalue=50.000000 minimp=50.000000 maximp=50.000000 favimp=50.000000
Width QSPI_9696 [InNetClass('QSPI')] p5: maxlimit=0.254 minlimit=0.089 preferedwidth=0.106 toplayer_minwidth=0.132 toplayer_maxwidth=0.132 toplayer_prefwidth=0.132 midlayer2_minwidth=0.113 midlayer2_maxwidth=0.113 midlayer2_prefwidth=0.113 midlayer3_minwidth=0.102 midlayer3_maxwidth=0.102 midlayer3_prefwidth=0.102 midlayer4_maxwidth=0.089 midlayer4_prefwidth=0.089 midlayer5_minwidth=0.106 midlayer5_maxwidth=0.106 midlayer6_minwidth=0.106 midlayer6_maxwidth=0.106 midlayer7_maxwidth=0.089 midlayer7_prefwidth=0.089 midlayer8_minwidth=0.102 midlayer8_maxwidth=0.102 midlayer8_prefwidth=0.102 midlayer9_minwidth=0.113 midlayer9_maxwidth=0.113 midlayer9_prefwidth=0.113 bottomlayer_minwidth=0.132 bottomlayer_maxwidth=0.132 bottomlayer_prefwidth=0.132 impedanceprofiledriven=TRUE impedanceprofileid={3A7C7114-273F-42D4-9E86-C85CF69E2638} impedanceprofilevalue=50.000000 minimp=50.000000 maximp=50.000000 favimp=50.000000
Width EMMC [InNetClass('EMMC_50')] p6: maxlimit=0.254 minlimit=0.089 preferedwidth=0.106 toplayer_minwidth=0.132 toplayer_maxwidth=0.132 toplayer_prefwidth=0.132 midlayer2_minwidth=0.113 midlayer2_maxwidth=0.113 midlayer2_prefwidth=0.113 midlayer3_minwidth=0.102 midlayer3_maxwidth=0.102 midlayer3_prefwidth=0.102 midlayer4_maxwidth=0.089 midlayer4_prefwidth=0.089 midlayer5_minwidth=0.106 midlayer5_maxwidth=0.106 midlayer6_minwidth=0.106 midlayer6_maxwidth=0.106 midlayer7_maxwidth=0.089 midlayer7_prefwidth=0.089 midlayer8_minwidth=0.102 midlayer8_maxwidth=0.102 midlayer8_prefwidth=0.102 midlayer9_minwidth=0.113 midlayer9_maxwidth=0.113 midlayer9_prefwidth=0.113 bottomlayer_minwidth=0.132 bottomlayer_maxwidth=0.132 bottomlayer_prefwidth=0.132 impedanceprofiledriven=TRUE impedanceprofileid={3A7C7114-273F-42D4-9E86-C85CF69E2638} impedanceprofilevalue=50.000000 minimp=50.000000 maximp=50.000000 favimp=50.000000
Width RAM2 [InNetClass('DRAM_2')] p7: maxlimit=0.254 minlimit=0.135 preferedwidth=0.17 toplayer_minwidth=0.203 toplayer_maxwidth=0.205 toplayer_prefwidth=0.205 midlayer2_minwidth=0.179 midlayer2_maxwidth=0.179 midlayer2_prefwidth=0.179 midlayer4_maxwidth=0.135 midlayer4_prefwidth=0.135 midlayer5_minwidth=0.17 midlayer5_maxwidth=0.17 midlayer6_minwidth=0.17 midlayer6_maxwidth=0.17 midlayer7_maxwidth=0.135 midlayer7_prefwidth=0.135 midlayer9_minwidth=0.179 midlayer9_maxwidth=0.179 midlayer9_prefwidth=0.179 bottomlayer_minwidth=0.203 bottomlayer_maxwidth=0.205 bottomlayer_prefwidth=0.205 impedanceprofiledriven=TRUE impedanceprofileid={C23675D0-44B1-47A6-9855-CDCFE64B82FE} impedanceprofilevalue=40.000000 minimp=50.000000 maximp=50.000000 favimp=50.000000
Width RAM1 [InNetClass('DRAM_1')] p8: maxlimit=0.254 minlimit=0.135 preferedwidth=0.17 toplayer_minwidth=0.203 toplayer_maxwidth=0.205 toplayer_prefwidth=0.205 midlayer2_minwidth=0.179 midlayer2_maxwidth=0.179 midlayer2_prefwidth=0.179 midlayer4_maxwidth=0.135 midlayer4_prefwidth=0.135 midlayer5_minwidth=0.17 midlayer5_maxwidth=0.17 midlayer6_minwidth=0.17 midlayer6_maxwidth=0.17 midlayer7_maxwidth=0.135 midlayer7_prefwidth=0.135 midlayer9_minwidth=0.179 midlayer9_maxwidth=0.179 midlayer9_prefwidth=0.179 bottomlayer_minwidth=0.203 bottomlayer_maxwidth=0.205 bottomlayer_prefwidth=0.205 impedanceprofiledriven=TRUE impedanceprofileid={C23675D0-44B1-47A6-9855-CDCFE64B82FE} impedanceprofilevalue=40.000000 minimp=50.000000 maximp=50.000000 favimp=50.000000
Width DP_GMAC [InNetClass('DP_50Ohms')] p9: maxlimit=0.254 minlimit=0.089 preferedwidth=0.106 toplayer_minwidth=0.132 toplayer_maxwidth=0.132 toplayer_prefwidth=0.132 midlayer2_minwidth=0.113 midlayer2_maxwidth=0.113 midlayer2_prefwidth=0.113 midlayer3_minwidth=0.102 midlayer3_maxwidth=0.102 midlayer3_prefwidth=0.102 midlayer4_maxwidth=0.089 midlayer4_prefwidth=0.089 midlayer5_minwidth=0.106 midlayer5_maxwidth=0.106 midlayer6_minwidth=0.106 midlayer6_maxwidth=0.106 midlayer7_maxwidth=0.089 midlayer7_prefwidth=0.089 midlayer8_minwidth=0.102 midlayer8_maxwidth=0.102 midlayer8_prefwidth=0.102 midlayer9_minwidth=0.113 midlayer9_maxwidth=0.113 midlayer9_prefwidth=0.113 bottomlayer_minwidth=0.132 bottomlayer_maxwidth=0.132 bottomlayer_prefwidth=0.132 impedanceprofiledriven=TRUE impedanceprofileid={3A7C7114-273F-42D4-9E86-C85CF69E2638} impedanceprofilevalue=50.000000 minimp=50.000000 maximp=50.000000 favimp=50.000000
Width RPI_QSPI [InNetClass('QSPI_RPI')] p10: maxlimit=0.254 minlimit=0.132 preferedwidth=0.254 toplayer_maxwidth=0.132 toplayer_prefwidth=0.132 bottomlayer_maxwidth=0.132 bottomlayer_prefwidth=0.132 minimp=50.000000 maximp=50.000000 favimp=50.000000
Width [All] p11: maxlimit=1.27 minlimit=0.089 preferedwidth=0.089 minimp=50.000000 maximp=50.000000 favimp=50.000000
22 further rules are at their usual default settings.

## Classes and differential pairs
net class DP_50Ohms_RX_: GMAC0_RXCLK GMAC0_RXD0 GMAC0_RXD1 GMAC0_RXD2 GMAC0_RXD3 GMAC0_RXDV_CRS GMAC0_TXCLK GMAC0_TXD0 GMAC0_TXD1 GMAC0_TXD2 GMAC0_TXD3 GMAC0_TXEN NetR187_2 NetR216_2 NetR217_2 NetR218_2 NetR219_2 NetR221_2 NetR222_2 NetR223_2 NetR224_2 NetR225_2 NetR226_2 NetR227_2
net class DP_50Ohms_TX: GMAC1_RXCLK GMAC1_RXD0 GMAC1_RXD1 GMAC1_RXD2 GMAC1_RXD3 GMAC1_RXDV_CRS GMAC1_TXCLK GMAC1_TXD0 GMAC1_TXD1 GMAC1_TXD2 GMAC1_TXD3 GMAC1_TXEN NetR189_2 NetR220_2 NetR236_2 NetR237_2 NetR238_2 NetR239_2 NetR240_2 NetR241_2 NetR243_2 NetR244_2 NetR245_2 NetR246_2
net class RK_50OHM: BOOT_SARADC_IN0_ CPU_BIG1_VSEL GND HDMITX0_HPDIN_M0 I2C0_SCL_M2 I2C0_SDA_M2 I2C1_SCL_M2 I2C1_SDA_M2 I2C6_SCL_M0 I2C6_SDA_M0 LCD_PWREN_H NetJ9_1 NetJ9_2 NetJ9_3 NetJ9_4 NetJ9_5 NetJ9_6 NetJ9_7 NetJ9_8 NetJ9_9 NetJ9_10 NetJ9_11 NetJ9_12 NetJ10_1 NetJ10_2 NetJ10_3 NetJ10_4 NetJ10_5 NetJ10_6 NetJ10_9 NetJ10_10 NetJ10_11 NetJ10_12 NetR3_2 NetR164_2 NetR165_2 NetR177_2 NetR178_1 NetR179_2 NetR180_1 NetR181_2 NetR182_1 NetR183_2 NetU3_A24 NetU3_A25 NetU3_A26 NetU3_AA27 NetU3_AB28 NetU3_AG24 NetU3_AG25 NetU3_AH27 NetU3_E25 NetU3_E26 NetU3_P30 NetU3_R30 NetU3_T28 NetU3_T29 NetU3_T31 NPU_VSEL PMIC_PWR_CTRL2 PWRON_L RESET_L SARADC_VIN1_KEY/RECOVERY SYS4V0_MODE_L UART2_RX_M0_DEBUG UART2_TX_M0_DEBUG VCC_1V8_S0
net class RGMII_TX: TX_CLK TX_ER TXD0 TXD1 TXD2 TXD3
net class RGMII_RX: CLK125EN MODE0 MODE1 MODE2 MODE3 MODE4
differential pair class MDI: P28.A P28.B P28.C P28.D
net class EMMC_9696: EMMC.CLK EMMC.CMD EMMC.D0 EMMC.D1 EMMC.D2 EMMC.D3 EMMC.D4 EMMC.D5 EMMC.D6 EMMC.D7 EMMC.RSTn
net class EMMC_50: EMMC_CLK eMMC_DATA_STROBE eMMC_RSTn NetR56_2 NetR57_2 NetR58_2 NetR59_2 NetR60_2 NetR61_2 NetR62_2 NetR63_2 NetR64_2
differential pair class HDMI_100: HDMI0_TX0_PORT HDMI0_TX0_PORT/eDP0_TX_D0 HDMI0_TX1_PORT HDMI0_TX1_PORT/eDP0_TX_D1 HDMI0_TX2_PORT HDMI0_TX2_PORT/eDP0_TX_D2 HDMI0_TX3_PORT HDMI0_TX3_PORT/eDP0_TX_D3 HDMI0_TX_SBD/eDP0_TX_AUX
differential pair class 90Ohm: _TYPEC0_OTG_D _TYPEC0_SSRX1 _TYPEC0_SSTX1 _TYPEC1_OTG__D _TYPEC1_OTG_D TYPEC0_OTG_D TYPEC0_SSRX1 TYPEC0_SSTX1 TYPEC1_OTG_D
differential pair class 100R_VS: _FIBRI0 _FIBRI1 _FIBRO0 _FIBRO1 _RD0_VS _TD0_VS FIBRI0 FIBRI1 FIBRO0 FIBRO1 RD0_VS REFCLK TD0_VS
net class 100R_VS: _FIBRI0_N _FIBRI0_P _FIBRI1_N _FIBRI1_P _FIBRO0_N _FIBRO0_P _FIBRO1_N _FIBRO1_P _RD0_VS_N _RD0_VS_P _TD0_VS_N _TD0_VS_P FIBRI0_N FIBRI0_P FIBRI1_N FIBRI1_P FIBRO0_N FIBRO0_P FIBRO1_N FIBRO1_P RD0_VS_N RD0_VS_P REFCLK_N REFCLK_P TD0_VS_N TD0_VS_P
net class 100Ohm: RD0_VS_N RD0_VS_P TD0_VS_N TD0_VS_P
differential pair class RAM_80: DDR_CH0_CLK_A DDR_CH0_CLK_B DDR_CH0_DQS0_A DDR_CH0_DQS0_B DDR_CH0_DQS1_A DDR_CH0_DQS1_B DDR_CH1_CLK_C DDR_CH1_CLK_D DDR_CH1_DQS0_C DDR_CH1_DQS0_D DDR_CH1_DQS1_C DDR_CH1_DQS1_D
differential pair class DBG_UART: _USB_ USB
net class DRAM_2: DDR_CH0_A0_A DDR_CH0_A0_B DDR_CH0_A1_A DDR_CH0_A1_B DDR_CH0_A2_A DDR_CH0_A2_B DDR_CH0_A3_A DDR_CH0_A3_B DDR_CH0_A4_A DDR_CH0_A4_B DDR_CH0_A5_A DDR_CH0_A5_B DDR_CH0_DM0_A DDR_CH0_DM0_B DDR_CH0_DM1_A DDR_CH0_DM1_B DDR_CH0_DQ0_A DDR_CH0_DQ0_B DDR_CH0_DQ1_A DDR_CH0_DQ1_B DDR_CH0_DQ2_A DDR_CH0_DQ2_B DDR_CH0_DQ3_A DDR_CH0_DQ3_B DDR_CH0_DQ4_A DDR_CH0_DQ4_B DDR_CH0_DQ5_A DDR_CH0_DQ5_B DDR_CH0_DQ6_A DDR_CH0_DQ6_B DDR_CH0_DQ7_A DDR_CH0_DQ7_B DDR_CH0_DQ8_A DDR_CH0_DQ8_B DDR_CH0_DQ9_A DDR_CH0_DQ9_B DDR_CH0_DQ10_A DDR_CH0_DQ10_B DDR_CH0_DQ11_A DDR_CH0_DQ11_B DDR_CH0_DQ12_A DDR_CH0_DQ12_B DDR_CH0_DQ13_A DDR_CH0_DQ13_B DDR_CH0_DQ14_A DDR_CH0_DQ14_B DDR_CH0_DQ15_A DDR_CH0_DQ15_B DDR_CH0_LP4/4X_CS0_A DDR_CH0_LP4/4X_CS0_B DDR_CH0_LP4/4X_CS1_A DDR_CH0_LP4/4X_CS1_B
net class DRAM_1: DDR_CH1_A0_C DDR_CH1_A0_D DDR_CH1_A1_C DDR_CH1_A1_D DDR_CH1_A2_C DDR_CH1_A2_D DDR_CH1_A3_C DDR_CH1_A3_D DDR_CH1_A4_C DDR_CH1_A4_D DDR_CH1_A5_C DDR_CH1_A5_D DDR_CH1_DM0_C DDR_CH1_DM0_D DDR_CH1_DM1_C DDR_CH1_DM1_D DDR_CH1_DQ0_C DDR_CH1_DQ0_D DDR_CH1_DQ1_C DDR_CH1_DQ1_D DDR_CH1_DQ2_C DDR_CH1_DQ2_D DDR_CH1_DQ3_C DDR_CH1_DQ3_D DDR_CH1_DQ4_C DDR_CH1_DQ4_D DDR_CH1_DQ5_C DDR_CH1_DQ5_D DDR_CH1_DQ6_C DDR_CH1_DQ6_D DDR_CH1_DQ7_C DDR_CH1_DQ7_D DDR_CH1_DQ8_C DDR_CH1_DQ8_D DDR_CH1_DQ9_C DDR_CH1_DQ9_D DDR_CH1_DQ10_C DDR_CH1_DQ10_D DDR_CH1_DQ11_C DDR_CH1_DQ11_D DDR_CH1_DQ12_C DDR_CH1_DQ12_D DDR_CH1_DQ13_C DDR_CH1_DQ13_D DDR_CH1_DQ14_C DDR_CH1_DQ14_D DDR_CH1_DQ15_C DDR_CH1_DQ15_D DDR_CH1_LP4/4X_CS0_C DDR_CH1_LP4/4X_CS0_D DDR_CH1_LP4/4X_CS1_C DDR_CH1_LP4/4X_CS1_D
net class DP_50Ohms: GMAC0_MCLKINOUT GMAC0_MDC GMAC0_MDIO GMAC0_RSTn_L GMAC0_RXCLK GMAC0_RXD0 GMAC0_RXD1 GMAC0_RXD2 GMAC0_RXD3 GMAC0_RXDV_CRS GMAC0_TXCLK GMAC0_TXD0 GMAC0_TXD1 GMAC0_TXD2 GMAC0_TXD3 GMAC0_TXEN GMAC1_MCLKINOUT GMAC1_MDC GMAC1_MDIO GMAC1_RSTn_L GMAC1_RXCLK GMAC1_RXD0 GMAC1_RXD1 GMAC1_RXD2 GMAC1_RXD3 GMAC1_RXDV_CRS GMAC1_TXCLK GMAC1_TXD0 GMAC1_TXD1 GMAC1_TXD2 GMAC1_TXD3 GMAC1_TXEN NetTP6_1 NetTP7_1
net class QSPI_RPI: QSPI_CLK QSPI_SD0 QSPI_SD1 QSPI_SD2 QSPI_SD3 QSPI_SS
differential pair class RP_USB: RP_D RPD
component class VSC_DP: C24 C25 C26 C27 C28 C29 C186 C187 C188 C189 C202 C490 C522 C523 C524 C525 C526 C527 C528 C529 C530 C531 C532 C533 C534 C535 C536 C537 C593 C594 C595 C596 C598 C599 C602 C603 C604 C605 C606 C607 C608 C609 C610 C611 C613 C614 C615 C616 C617 C618 C619 C620 C621 C622 C623 C624 C625 C626 C627 C628 C629 C630 C631 C633 C634 C649 C650 C651 C652 C653 C654 C655 C656 C657 C658 C659 C660 C661 C662 C663 C664 C665 C666 C667 C668 C669 C670 C671 C672 C673 C674 C675 C676 C677 C678 C679 C680 C681 C682 L15 L24 L26 L27 L28 P4 P5 R43 R50 R52 R53 R54 R161 R162 R163 R187 R189 R215 R216 R217 R218 R219 R220 R221 R222 R223 R224 R225 R226 R227 R228 R229 R231 R232 R233 R234 R235 R236 R237 R238 R239 R240 R241 R242 R243 R244 R245 R246 R249 R250 R251 R252 R254 R255 R256 R257 R258 R259 R260 R261 R262 R266 R267 R268 R269 R270 R271 TP8 U9 U47 U48 U49 U50 U51 U52 U53 Y2 Y3 Y4
component class RP2350: C451 C453 C542 C559 C560 C561 C562 C563 C564 C565 C566 C567 C568 C569 C570 C571 C572 C573 C574 D5 D6 L25 P2 P3 R188 R190 R191 R192 R193 R194 R195 R196 R197 R198 R199 R200 R201 R202 R203 R204 SW10 SW11 TP9 U35 U37 U41 U63 USBC1
component class Level_Shifter: C641 C642 C643 C644 C645 C646 C647 C648 IC IC1 R276 R277 R278 R279 R280 R281 R282 R283 R284 R285 U55 U56 U57 U58 U59 U60 U61
component class IO_Expander_of_RP: C575 C576 C577 C578 C579 C580 C581 C582 C583 C584 C585 C586 C587 C588 C589 C590 C591 C592 D13 D16 J8 Q14 Q15 Q16 Q17 R205 R206 R207 R208 R209 R210 R211 R212 R213 R214 U42 U43 U44 U46
component class "Key Array": R177 R178 R179 R180 R181 R182 R183 SW3 SW4 SW5 SW6 SW7 SW8 SW9 U16 U17 U29 U33
component class LPDDR4_EDA: C315 C316 C317 C318 C319 C320 C322 C323 C324 C325 C327 C328 C331 C332 C333 C334 C335 C336 C337 C338 C339 C340 C341 C342 C344 C345 C346 C356 C357 C358 C359 C360 C361 C362 C363 C364 C365 C366 C367 C368 C388 C392 C393 C394 C395 C396 C397 C398 C399 C400 C401 C402 C403 C404 C405 C406 C407 C408 C409 C410 C411 C412 C413 C414 C415 C416 C417 C418 C419 C420 C421 C422 C423 C424 C425 C426 C427 C428 C429 C430 C431 C432 C433 C551 R27 R44 R45 R46 R47 R48 R49 R51 R71 R150 R151 R152 R153 R154 R155 R156 R263 R264 R265 TP62 TP63 TP64 TP81 TP82 TP83 U12 U15
differential pair class PCIe: PCIE_RX PCIE_TX PCIE_TX_C
differential pair class Clock: CK_LAN PCIE_CLK
net class QSPI: QSPI.CK QSPI.D0 QSPI.D1 QSPI.D2 QSPI.D3 QSPI.nCS
net class Power: 0V9 1V2 1V8 2V5 12V NetC109_2 VCC1 VDDH18 VDDH18_PCIE VDDHS VDDHS_PCIE VDDHV VDDHV_PCIE VDDPLLDDR
net class MDI: P28.A_N P28.A_P P28.B_N P28.B_P P28.C_N P28.C_P P28.D_N P28.D_P
net class HiSpeed: CK_LAN_N CK_LAN_P NetC90_2 NetC91_2 NetC92_1 NetC93_1 NetU5_A4 NetU5_B4 NetU5_V17 NetU5_W17 PCIE_CLK_N PCIE_CLK_P PCIE_RX_N PCIE_RX_P PCIE_TX_C_N PCIE_TX_C_P PCIE_TX_N PCIE_TX_P
component class "SPI _NOR": R72 R73 U7
component class "RS232 DBG_UART": C541 C543 C544 C545 C546 C547 C548 C549 C550 P1 R164 R165 R166 R167 R168 R169 R170 R171 U8 U30 U31 U32 USB1
component class RK3588_USB2.0_USB3.0: C454 C455 C456 C457 C458 C459 C460 C461 C462 J6 J7 L18 R74 R91 R92 R93 R94 R95 R96 R97 R98 R173 R174 R175 R176 TP67 TP68 U11 U13 U14
component class RK3588_Power: C18 C36 C37 C38 C220 C221 C222 C223 C224 C226 C227 C228 C229 C230 C231 C232 C233 C234 C235 C236 C237 C238 C239 C240 C241 C242 C243 C244 C245 C246 C247 C248 C249 C250 C251 C252 C253 C254 C255 C256 C257 C258 C259 C260 C261 C262 C263 C264 C265 C266 C267 C268 C269 C270 C271 C272 C273 C274 C275 C276 C277 C278 C279 C280 C281 C282 TP46 TP48 TP49 TP50 TP51 TP52 TP53 TP54
component class RK806-1: C41 C42 C43 C44 C45 C46 C49 C50 C51 C52 C53 C54 C55 C56 C57 C58 C59 C60 C61 C62 C63 C64 C65 C66 C67 C68 C69 C70 C71 C72 C73 C74 C75 C76 C77 C157 C158 C159 C160 C161 C162 C163 C164 C165 C166 C167 C168 C169 C170 C171 C172 C173 C174 C175 C176 C177 C178 C179 C180 C181 C314 C350 C425 C442 C444 C446 C552 C553 C554 C555 C556 C557 C558 C637 D1 D2 L1 L2 L3 L4 L5 L7 L10 L11 L12 L13 R28 R29 R30 R31 R32 R33 R34 R35 R36 R37 R38 R39 R40 R41 R148 R149 R172 R247 R248 R286 R287 R288 R289 R290 R291 R292 R293 TP10 TP13 TP14 TP15 TP17 TP18 TP22 TP25 TP28 TP29 TP31 TP35 TP36 TP37 TP38 TP39 U5
component class rk3588_LPDDR4: C283 C284 C285 C286 C287 C288 C289 C290 C291 C292 C293 C294 C295 C296 C297 C298 C299 C300 C301 C302 C303 C304 C305 C306 C307 C308 C309 C310 C311 C312 R70 R274 R275 R303 TP55 TP56 TP57 TP59 TP60 TP61 U3
component class rk3588: C5 C15 C16 C17 C23 C30 C31 C32 C33 C34 C35 C203 C204 C612 C632 C683 C684 C685 C686 IC2 J5 J9 J10 R3 R9 R20 R23 R24 R25 R26 R128 R130 R253 R272 R273 R301 R304 R305 R306 TP2 TP6 TP7 U54 X1
component class 8841: C313 C369 C370 C371 C372 C373 C374 C375 C376 C377 C378 C379 C380 C381 C382 C383 C384 C385 C386 C387 C389 C390 C391 FB24 FB25 FB26 J333 R374 R375 R376 R377 R381 R382 R383 R384 R385 R386 R387 R388 R389 R390 R391 R392 R393 R394 R395 R396 R397 R398 R399 R400 R401 R402 U45
component class LAN9696_Supply: C78 C79 C80 C81 C82 C83 C84 C85 C86 C87 C88 C89 C90 C91 C92 C93 C94 C95 C96 C97 C98 C99 C100 C101 C102 C103 C104 C105 C106 C107 C108 C109 C110 C111 C112 C113 C114 C115 C116 C117 C118 C119 C120 C121 C122 C123 C124 C125 C126 C127 C128 C129 C130 C131 C132 C133 C134 C135 C136 C137 C138 C139 C140 C141 C142 C143 C144 C145 C146 C147 C148 C149 C150 C151 C152 C153 C154 C155 C156 C183 C190 C191 FB1 FB2 FB3 FB4 FB5 FB6 FB7 R101
component class LAN9696: C1 C2 C3 C4 C6 C7 C8 C9 C10 C11 C12 C13 C14 C182 D3 J1 J2 J3 J34 R1 R2 R4 R5 R6 R7 R8 R10 R11 R12 R13 R14 R15 R16 R17 R18 R19 R21 R22 R42 SW1 TP41 U1 U2 U4
component class HDMI: C463 C464 C465 C466 C467 C468 C469 C470 C471 C472 C473 C474 C475 C476 C477 C478 C479 C480 C481 C482 D4 D7 HDMI1 Q4 Q5 Q6 Q7 Q8 Q9 Q10 Q11 Q12 R99 R100 R102 R103 R104 R105 R106 R107 R108 R109 R110 R111 R112 R113 R114 R115 R116 R117 R118 R119 U20 U21
component class EMMC: C207 C208 C209 C210 C211 C212 C213 C214 C215 C216 C217 R56 R57 R58 R59 R60 R61 R62 R63 R64 R65 R66 R67 R68 R69 TP42 TP43 TP45 U10
component class "Discrete Power": 5 6 C485 C493 C494 C495 C496 C497 C498 C499 C500 C501 C502 C503 C504 C505 C506 C507 C508 C509 C510 C511 C512 C513 C514 C515 C516 C517 C518 C519 C520 C521 FB9 L19 L20 L21 L22 R120 R121 R122 R123 R124 R125 R126 R127 R129 R131 R132 R133 R134 R135 R307 R308 R309 TP71 TP72 TP74 TP75 TP76 U22 U23 U24 U25 U26 U27
component class BoardSupply: 1 2 3 4 C39 C40 C192 C193 C196 C197 C198 C199 C200 C201 C205 C218 C219 C225 C434 C435 C436 C439 C440 C441 C443 C445 C448 C449 C450 C452 CN1 D9 L16 L17 L29 Q3 Q13 Q18 R75 R76 R77 R78 R79 R80 R81 R82 R83 R84 R85 R86 R87 R88 R89 R90 R294 R295 R296 R297 R298 R299 R300 R302 TP16 TP20 TP23 TP65 TP66 U18 U19 U62
component class ATE_Safety: U6
component class LAN_Supply: C19 C20 C21 C22 C47 C48 C184 C185 C194 C195 C206 C321 C326 C329 C330 C343 C347 C348 C349 C351 C352 C353 C354 C355 C437 C438 C447 C483 C484 C486 C487 C488 C489 C491 C492 C538 C539 C540 C597 C600 C601 C635 C636 C638 C639 C640 FB10 FB11 FB12 FB13 J12 J13 J14 JP1 L6 L8 L9 L14 L23 LABEL1 R55 R136 R137 R138 R139 R140 R141 R142 R143 R144 R145 R146 R147 R157 R158 R159 R160 R184 R185 R186 R230 R334 R335 R339 TP21 U28 U34 U36 U38 U39 U40
differential pair REFCLK: +REFCLK_P -REFCLK_N
differential pair HDMI0_TX_SBD/eDP0_TX_AUX: +HDMI0_TX_SBD/eDP0_TX_AUX_P -HDMI0_TX_SBD/eDP0_TX_AUX_N
differential pair HDMI0_TX3_PORT/eDP0_TX_D3: +HDMI0_TX3_PORT/eDP0_TX_D3_P -HDMI0_TX3_PORT/eDP0_TX_D3_N
differential pair HDMI0_TX3_PORT: +HDMI0_TX3_PORT_P -HDMI0_TX3_PORT_N
differential pair HDMI0_TX2_PORT/eDP0_TX_D2: +HDMI0_TX2_PORT/eDP0_TX_D2_P -HDMI0_TX2_PORT/eDP0_TX_D2_N
differential pair HDMI0_TX2_PORT: +HDMI0_TX2_PORT_P -HDMI0_TX2_PORT_N
differential pair HDMI0_TX1_PORT/eDP0_TX_D1: +HDMI0_TX1_PORT/eDP0_TX_D1_P -HDMI0_TX1_PORT/eDP0_TX_D1_N
differential pair HDMI0_TX1_PORT: +HDMI0_TX1_PORT_P -HDMI0_TX1_PORT_N
differential pair HDMI0_TX0_PORT/eDP0_TX_D0: +HDMI0_TX0_PORT/eDP0_TX_D0_P -HDMI0_TX0_PORT/eDP0_TX_D0_N
differential pair HDMI0_TX0_PORT: +HDMI0_TX0_PORT_P -HDMI0_TX0_PORT_N
differential pair TYPEC0_SSTX1: +TYPEC0_SSTX1_P -TYPEC0_SSTX1_N
differential pair TYPEC0_SSRX1: +TYPEC0_SSRX1_P -TYPEC0_SSRX1_N
differential pair TYPEC0_OTG_D: +TYPEC0_OTG_D_P -TYPEC0_OTG_D_N
differential pair _TYPEC1_OTG_D: +_TYPEC1_OTG_D_P -_TYPEC1_OTG_D_N
differential pair _TYPEC1_OTG__D: +_TYPEC1_OTG__D_P -_TYPEC1_OTG__D_N
differential pair _TYPEC0_SSTX1: +_TYPEC0_SSTX1_P -_TYPEC0_SSTX1_N
differential pair _TYPEC0_SSRX1: +_TYPEC0_SSRX1_P -_TYPEC0_SSRX1_N
differential pair _TYPEC0_OTG_D: +_TYPEC0_OTG_D_P -_TYPEC0_OTG_D_N
differential pair _FIBRI1: +_FIBRI1_P -_FIBRI1_N
differential pair _FIBRI0: +_FIBRI0_P -_FIBRI0_N
differential pair _FIBRO1: +_FIBRO1_P -_FIBRO1_N
differential pair _FIBRO0: +_FIBRO0_P -_FIBRO0_N
differential pair _TD0_VS: +_TD0_VS_P -_TD0_VS_N
differential pair _RD0_VS: +_RD0_VS_P -_RD0_VS_N
differential pair FIBRO1: +FIBRO1_P -FIBRO1_N
differential pair FIBRO0: +FIBRO0_P -FIBRO0_N
differential pair FIBRI1: +FIBRI1_P -FIBRI1_N
differential pair FIBRI0: +FIBRI0_P -FIBRI0_N
differential pair TD0_VS: +TD0_VS_P -TD0_VS_N
differential pair RD0_VS: +RD0_VS_P -RD0_VS_N
differential pair DDR_CH1_DQS1_D: +DDR_CH1_DQS1_D_P -DDR_CH1_DQS1_D_N
differential pair DDR_CH1_DQS1_C: +DDR_CH1_DQS1_C_P -DDR_CH1_DQS1_C_N
differential pair DDR_CH1_DQS0_D: +DDR_CH1_DQS0_D_P -DDR_CH1_DQS0_D_N
differential pair DDR_CH1_DQS0_C: +DDR_CH1_DQS0_C_P -DDR_CH1_DQS0_C_N
differential pair DDR_CH1_CLK_D: +DDR_CH1_CLK_D_P -DDR_CH1_CLK_D_N
differential pair DDR_CH1_CLK_C: +DDR_CH1_CLK_C_P -DDR_CH1_CLK_C_N
differential pair DDR_CH0_DQS1_B: +DDR_CH0_DQS1_B_P -DDR_CH0_DQS1_B_N
differential pair DDR_CH0_DQS1_A: +DDR_CH0_DQS1_A_P -DDR_CH0_DQS1_A_N
differential pair DDR_CH0_DQS0_B: +DDR_CH0_DQS0_B_P -DDR_CH0_DQS0_B_N
differential pair DDR_CH0_DQS0_A: +DDR_CH0_DQS0_A_P -DDR_CH0_DQS0_A_N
